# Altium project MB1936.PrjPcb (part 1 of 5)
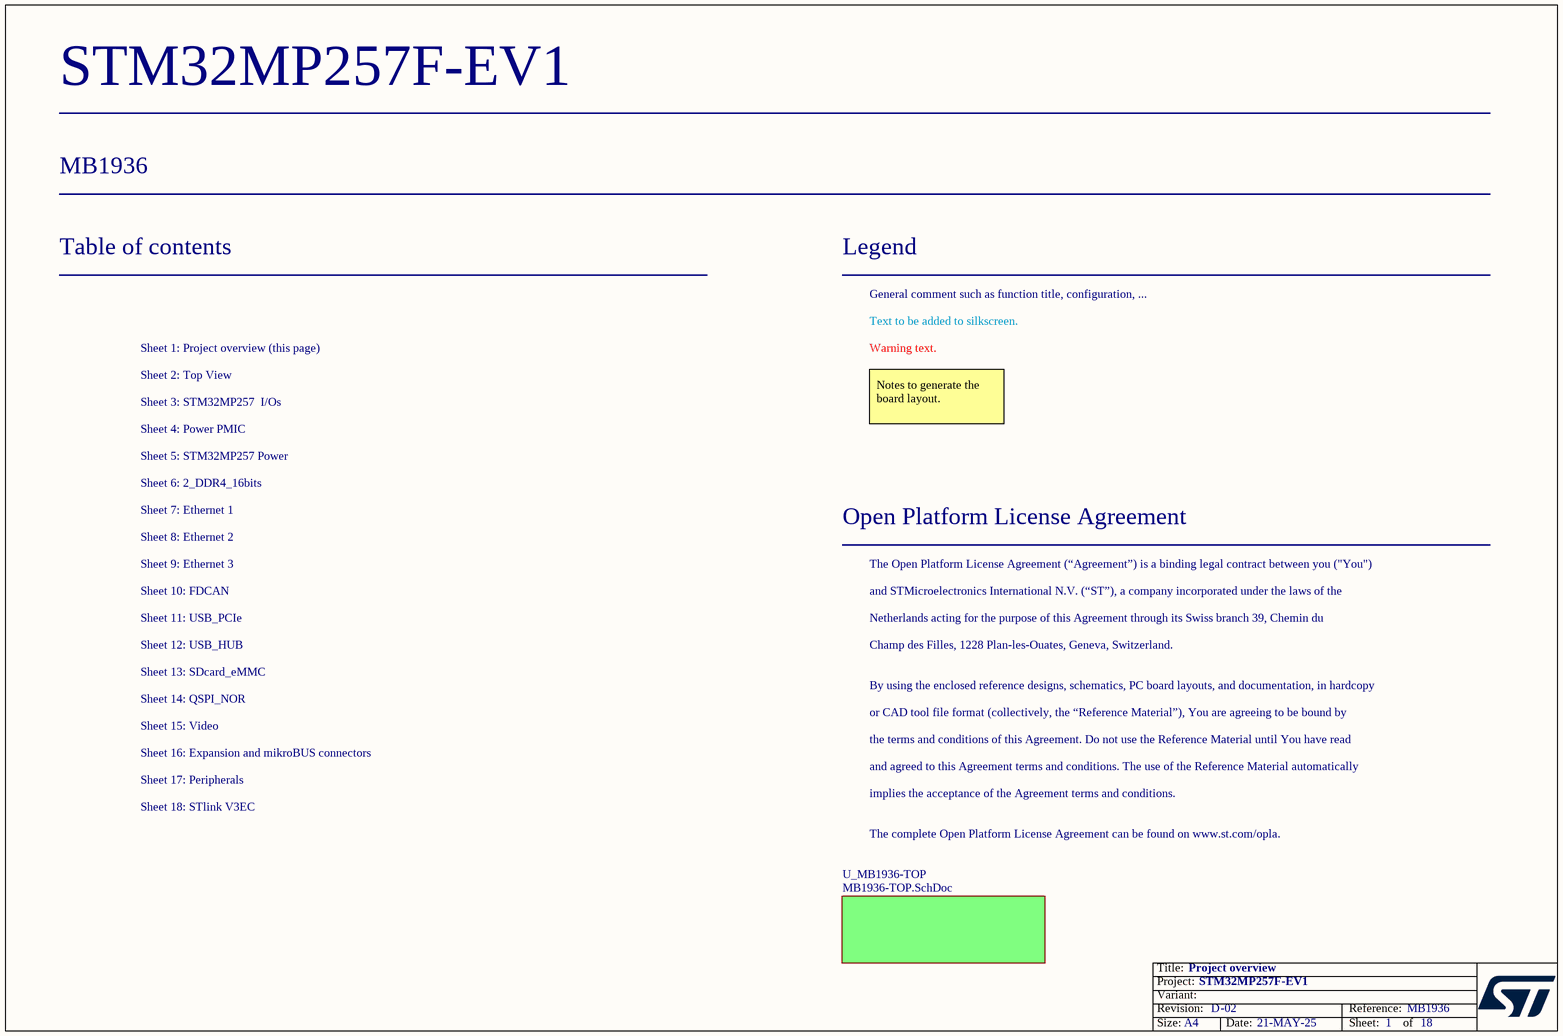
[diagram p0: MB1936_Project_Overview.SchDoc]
Board_Assembly_Revision: 02; Board_Document_Date: 21-MAY-25; Board_Name: STM32MP257F-EV1; Board_PCB_Revision: D; Board_Reference: MB1936
18 sheets, 865 parts. Net scope: flat (ports and power ports of the same name join across sheets).
Board file: MB1936.PcbDoc
Sheets:
  MB1936_Project_Overview.SchDoc
    U_MB1936-TOP = MB1936-TOP.SchDoc
      U_Video = Video.SchDoc
      U_SDcard_eMMC = SDcard_eMMC.SchDoc
      U_MP257_18x18 = MP257_18x18.SchDoc
      U_FDCAN = FDCAN.SchDoc
      U_Ethernet1 = Ethernet1.SchDoc
      U_Ethernet2 = Ethernet2.SchDoc
      U_Ethernet3 = Ethernet3.SchDoc
      U_Peripherals = Peripherals.SchDoc
      U_QSPI_NOR = QSPI_NOR.SchDoc
      U_Power_MPU = Power_MPU.SchDoc
      U_USB_HUB = USB_HUB.SchDoc
      U_2_DDR4_16bits = 2_DDR4_16bits.SchDoc
      U_USB_PCIe = USB_PCIe.SchDoc
      U_STLINK_V3EC = STLINK_V3EC.SchDoc
      U_Power_PMIC = Power_PMIC.SchDoc
      U_Expansion _&_mikroBUS_Connectors = Expansion _&_mikroBUS_Connectors.SchDoc

## Sheet MB1936_Project_Overview.SchDoc: Project overview
size A4; Date: Not used; ApprovedBy: Not used; CheckedBy: Not used; Author: Not used; CompanyName: STMicroelectronics; DrawnBy: Not used; Engineer: Not used; Organization: Not used; Address1: Not used; Address2: Not used; Address3: Not used; Address4: Not used; DocumentNumber: Not used; Revision: Not used; SheetNumber: 1; SheetTotal: 18

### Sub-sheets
U_MB1936-TOP = MB1936-TOP.SchDoc: no entries

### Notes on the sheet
- Table of contents
- Legend
- General comment such as function title, configuration, ...
- Sheet 1: Project overview (this page)
- Sheet 2: Top View
- Text to be added to silkscreen.
- Warning text.
- Sheet 3: STM32MP257  I/Os
- Sheet 4: Power PMIC
- Notes to generate the board layout.
- Sheet 5: STM32MP257 Power
- Sheet 7: Ethernet 1
- Sheet 6: 2_DDR4_16bits
- Sheet 8: Ethernet 2
- Sheet 9: Ethernet 3
- Open Platform License Agreement
- The Open Platform License Agreement (“Agreement”) is a binding legal contract between you ("You")
- Sheet 10: FDCAN
- Sheet 11: USB_PCIe
- Sheet 12: USB_HUB
- and STMicroelectronics International N.V. (“ST”), a company incorporated under the laws of the
- Netherlands acting for the purpose of this Agreement through its Swiss branch 39, Chemin du
- Champ des Filles, 1228 Plan-les-Ouates, Geneva, Switzerland.
- Sheet 13: SDcard_eMMC
- Sheet 14: QSPI_NOR
- By using the enclosed reference designs, schematics, PC board layouts, and documentation, in hardcopy
- or CAD tool file format (collectively, the “Reference Material”), You are agreeing to be bound by
- Sheet 17: Peripherals
- Sheet 16: Expansion and mikroBUS connectors
- Sheet 15: Video
- the terms and conditions of this Agreement. Do not use the Reference Material until You have read
- and agreed to this Agreement terms and conditions. The use of the Reference Material automatically
- Sheet 18: STlink V3EC
- implies the acceptance of the Agreement terms and conditions.
- The complete Open Platform License Agreement can be found on www.st.com/opla.

## Sheet MB1936-TOP.SchDoc: TOP
size A3; Date: Not used; ApprovedBy: Not used; CheckedBy: Not used; Author: Not used; CompanyName: STMicroelectronics; DrawnBy: Not used; Engineer: Not used; Organization: Not used; Address1: Not used; Address2: Not used; Address3: Not used; Address4: Not used; DocumentNumber: Not used; Revision: Not used; SheetNumber: 2; SheetTotal: 18
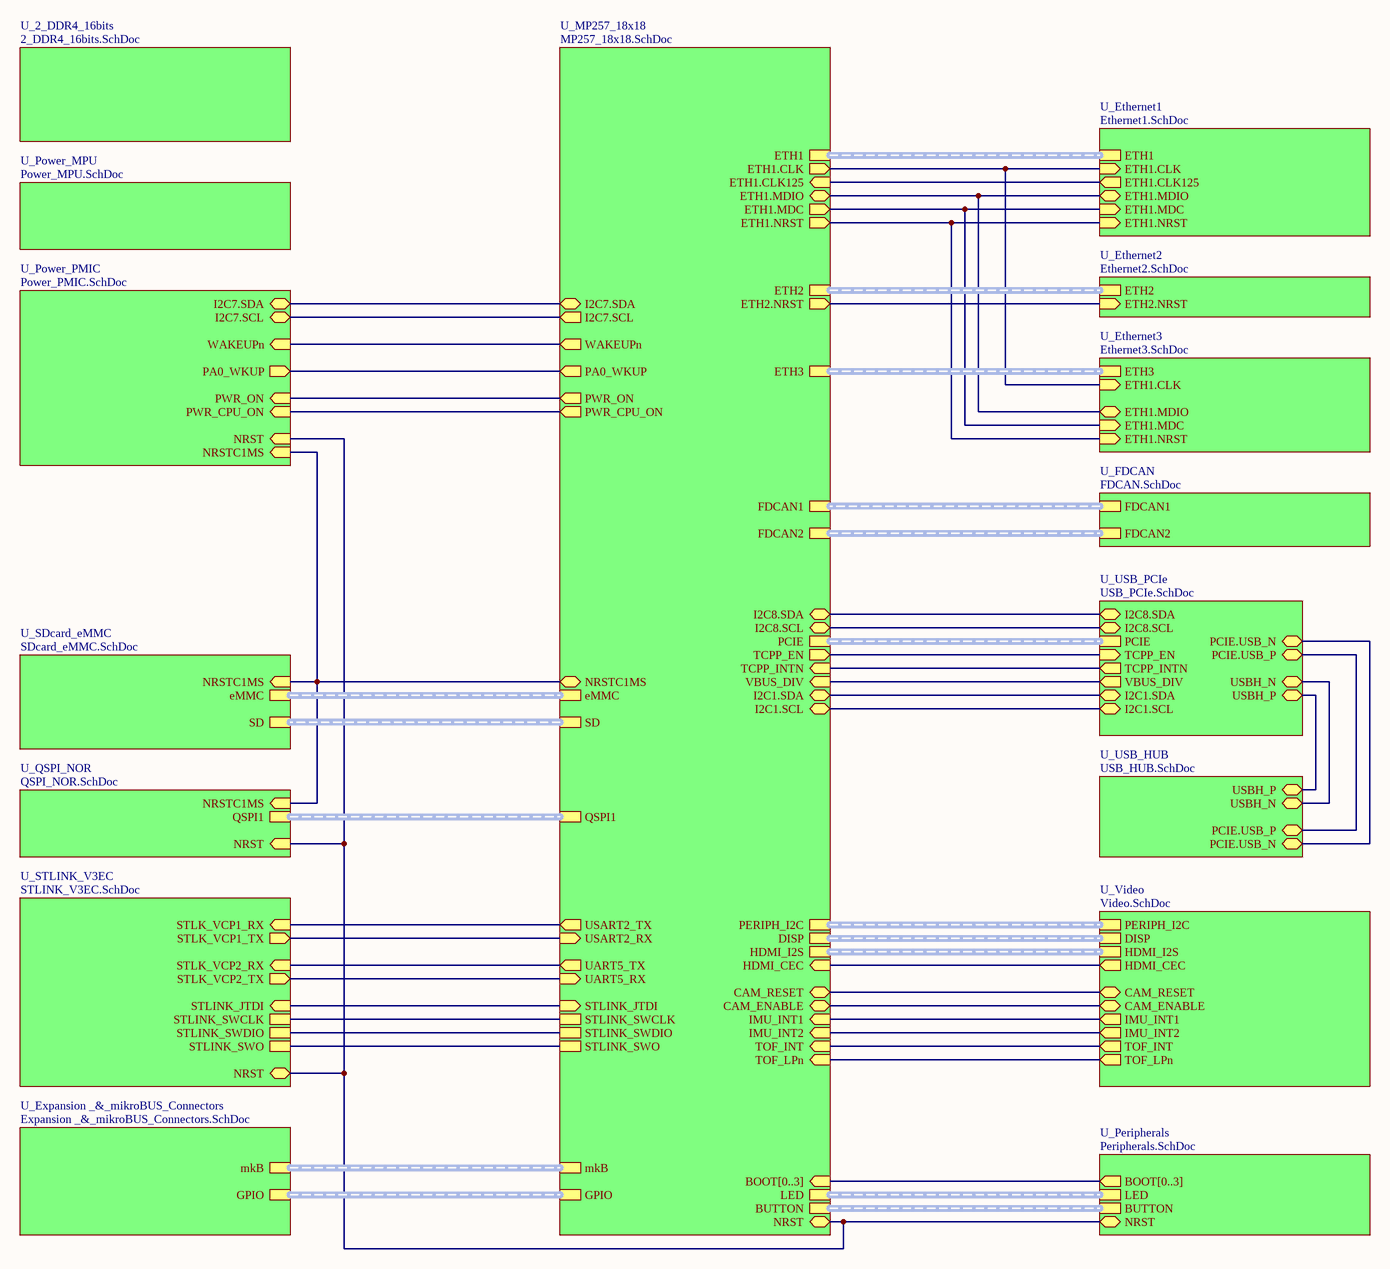
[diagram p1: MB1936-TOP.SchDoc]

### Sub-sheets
U_2_DDR4_16bits = 2_DDR4_16bits.SchDoc: no entries
U_Ethernet1 = Ethernet1.SchDoc: ETH1.NRST (in), ETH1 (harness ETH1), ETH1.CLK (in), ETH1.MDC (in), ETH1.MDIO (bidir), ETH1.CLK125 (out)
U_Ethernet2 = Ethernet2.SchDoc: ETH2.NRST (in), ETH2 (harness ETH2)
U_Ethernet3 = Ethernet3.SchDoc: ETH1.NRST (in), ETH3 (harness ETH3), ETH1.CLK (in), ETH1.MDIO (bidir), ETH1.MDC (in)
U_Expansion _&_mikroBUS_Connectors = Expansion _&_mikroBUS_Connectors.SchDoc: GPIO (harness GPIO), mkB (harness mikroBUS)
U_FDCAN = FDCAN.SchDoc: FDCAN2 (harness FDCAN2), FDCAN1 (harness FDCAN1)
U_MP257_18x18 = MP257_18x18.SchDoc: SD (harness SD), eMMC (harness eMMC), ETH1 (harness ETH1), ETH3 (harness ETH3), HDMI_CEC (in), ETH2 (harness ETH2), ETH1.NRST (out), PWR_ON (out), NRST (bidir), FDCAN1 (harness FDCAN1), FDCAN2 (harness FDCAN2), LED (harness LED), BOOT[0..3] (in), UART5_RX (in), UART5_TX (out), QSPI1 (harness QSPI), GPIO (harness GPIO), HDMI_I2S (harness HDMI_I2S), PERIPH_I2C (harness PERIPH_I2C), TCPP_INTN (in), I2C7.SDA (bidir), USART2_TX (out), I2C7.SCL (out), USART2_RX (in), VBUS_DIV (in), ETH1.MDIO (bidir), ETH1.CLK125 (in), ETH1.MDC (out), ETH1.CLK (out), PCIE (harness PCIE), STLINK_JTDI (in), STLINK_SWCLK, STLINK_SWDIO, STLINK_SWO, DISP (harness DISP), I2C1.SDA (bidir), I2C1.SCL (bidir), NRSTC1MS (bidir), PWR_CPU_ON (out), TOF_INT (in), CAM_ENABLE (bidir), IMU_INT1 (in), IMU_INT2 (in), TOF_LPn (in), CAM_RESET (bidir), ETH2.NRST (out), I2C8.SDA (bidir), I2C8.SCL (bidir), BUTTON (harness BUTTON), PA0_WKUP (out), WAKEUPn (out), mkB (harness mikroBUS), TCPP_EN (out)
U_Peripherals = Peripherals.SchDoc: NRST (bidir), BOOT[0..3] (out), LED (harness LED), BUTTON (harness BUTTON)
U_Power_MPU = Power_MPU.SchDoc: no entries
U_Power_PMIC = Power_PMIC.SchDoc: PWR_CPU_ON (in), NRST (in), PWR_ON (in), I2C7.SDA (bidir), I2C7.SCL (bidir), WAKEUPn (in), NRSTC1MS (in), PA0_WKUP (out)
U_QSPI_NOR = QSPI_NOR.SchDoc: QSPI1 (harness QSPI), NRSTC1MS (in), NRST (in)
U_SDcard_eMMC = SDcard_eMMC.SchDoc: SD (harness SD), NRSTC1MS (in), eMMC (harness eMMC)
U_STLINK_V3EC = STLINK_V3EC.SchDoc: NRST (bidir), STLK_VCP2_TX (out), STLK_VCP2_RX (in), STLK_VCP1_TX (out), STLK_VCP1_RX (in), STLINK_SWCLK, STLINK_SWDIO, STLINK_JTDI (in), STLINK_SWO
U_USB_HUB = USB_HUB.SchDoc: USBH_P (bidir), USBH_N (bidir), PCIE.USB_P (bidir), PCIE.USB_N (bidir)
U_USB_PCIe = USB_PCIe.SchDoc: PCIE (harness PCIE), USBH_P (bidir), USBH_N (bidir), TCPP_INTN (out), I2C1.SDA (bidir), I2C1.SCL (bidir), VBUS_DIV (out), PCIE.USB_N (bidir), PCIE.USB_P (bidir), I2C8.SDA (bidir), I2C8.SCL (bidir), TCPP_EN (in)
U_Video = Video.SchDoc: CAM_RESET (bidir), HDMI_CEC (out), CAM_ENABLE (bidir), HDMI_I2S (harness HDMI_I2S), PERIPH_I2C (harness PERIPH_I2C), DISP (harness DISP), IMU_INT1 (out), TOF_INT (out), TOF_LPn (out), IMU_INT2 (out)

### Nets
(unnamed): sheet U_Video/CAM_RESET, sheet U_MP257_18x18/CAM_RESET
(unnamed): sheet U_Video/HDMI_CEC, sheet U_MP257_18x18/HDMI_CEC  [a separate net that carries the same name]
(unnamed): sheet U_Video/CAM_ENABLE, sheet U_MP257_18x18/CAM_ENABLE  [a separate net that carries the same name]
(unnamed): sheet U_Video/IMU_INT1, sheet U_MP257_18x18/IMU_INT1  [a separate net that carries the same name]
(unnamed): sheet U_Video/TOF_INT, sheet U_MP257_18x18/TOF_INT  [a separate net that carries the same name]
(unnamed): sheet U_Video/TOF_LPn, sheet U_MP257_18x18/TOF_LPn  [a separate net that carries the same name]
(unnamed): sheet U_Video/IMU_INT2, sheet U_MP257_18x18/IMU_INT2  [a separate net that carries the same name]
(unnamed): sheet U_SDcard_eMMC/NRSTC1MS, sheet U_MP257_18x18/NRSTC1MS, sheet U_QSPI_NOR/NRSTC1MS, sheet U_Power_PMIC/NRSTC1MS  [a separate net that carries the same name]
(unnamed): sheet U_MP257_18x18/ETH1.NRST, sheet U_Ethernet1/ETH1.NRST, sheet U_Ethernet3/ETH1.NRST  [a separate net that carries the same name]
(unnamed): sheet U_MP257_18x18/PWR_ON, sheet U_Power_PMIC/PWR_ON  [a separate net that carries the same name]
(unnamed): sheet U_MP257_18x18/NRST, sheet U_Peripherals/NRST, sheet U_QSPI_NOR/NRST, sheet U_STLINK_V3EC/NRST, sheet U_Power_PMIC/NRST  [a separate net that carries the same name]
(unnamed): sheet U_MP257_18x18/UART5_RX, sheet U_STLINK_V3EC/STLK_VCP2_TX  [a separate net that carries the same name]
(unnamed): sheet U_MP257_18x18/UART5_TX, sheet U_STLINK_V3EC/STLK_VCP2_RX  [a separate net that carries the same name]
(unnamed): sheet U_MP257_18x18/TCPP_INTN, sheet U_USB_PCIe/TCPP_INTN  [a separate net that carries the same name]
(unnamed): sheet U_MP257_18x18/I2C7.SDA, sheet U_Power_PMIC/I2C7.SDA  [a separate net that carries the same name]
(unnamed): sheet U_MP257_18x18/USART2_TX, sheet U_STLINK_V3EC/STLK_VCP1_RX  [a separate net that carries the same name]
(unnamed): sheet U_MP257_18x18/I2C7.SCL, sheet U_Power_PMIC/I2C7.SCL  [a separate net that carries the same name]
(unnamed): sheet U_MP257_18x18/USART2_RX, sheet U_STLINK_V3EC/STLK_VCP1_TX  [a separate net that carries the same name]
(unnamed): sheet U_MP257_18x18/VBUS_DIV, sheet U_USB_PCIe/VBUS_DIV  [a separate net that carries the same name]
(unnamed): sheet U_MP257_18x18/ETH1.MDIO, sheet U_Ethernet1/ETH1.MDIO, sheet U_Ethernet3/ETH1.MDIO  [a separate net that carries the same name]
(unnamed): sheet U_MP257_18x18/ETH1.CLK125, sheet U_Ethernet1/ETH1.CLK125  [a separate net that carries the same name]
(unnamed): sheet U_MP257_18x18/ETH1.MDC, sheet U_Ethernet1/ETH1.MDC, sheet U_Ethernet3/ETH1.MDC  [a separate net that carries the same name]
(unnamed): sheet U_MP257_18x18/ETH1.CLK, sheet U_Ethernet1/ETH1.CLK, sheet U_Ethernet3/ETH1.CLK  [a separate net that carries the same name]
(unnamed): sheet U_MP257_18x18/STLINK_JTDI, sheet U_STLINK_V3EC/STLINK_JTDI  [a separate net that carries the same name]
(unnamed): sheet U_MP257_18x18/STLINK_SWCLK, sheet U_STLINK_V3EC/STLINK_SWCLK  [a separate net that carries the same name]
(unnamed): sheet U_MP257_18x18/STLINK_SWDIO, sheet U_STLINK_V3EC/STLINK_SWDIO  [a separate net that carries the same name]
(unnamed): sheet U_MP257_18x18/STLINK_SWO, sheet U_STLINK_V3EC/STLINK_SWO  [a separate net that carries the same name]
(unnamed): sheet U_MP257_18x18/I2C1.SDA, sheet U_USB_PCIe/I2C1.SDA  [a separate net that carries the same name]
(unnamed): sheet U_MP257_18x18/I2C1.SCL, sheet U_USB_PCIe/I2C1.SCL  [a separate net that carries the same name]
(unnamed): sheet U_MP257_18x18/PWR_CPU_ON, sheet U_Power_PMIC/PWR_CPU_ON  [a separate net that carries the same name]
(unnamed): sheet U_MP257_18x18/ETH2.NRST, sheet U_Ethernet2/ETH2.NRST  [a separate net that carries the same name]
(unnamed): sheet U_MP257_18x18/I2C8.SDA, sheet U_USB_PCIe/I2C8.SDA  [a separate net that carries the same name]
(unnamed): sheet U_MP257_18x18/I2C8.SCL, sheet U_USB_PCIe/I2C8.SCL  [a separate net that carries the same name]
(unnamed): sheet U_MP257_18x18/PA0_WKUP, sheet U_Power_PMIC/PA0_WKUP  [a separate net that carries the same name]
(unnamed): sheet U_MP257_18x18/WAKEUPn, sheet U_Power_PMIC/WAKEUPn  [a separate net that carries the same name]
(unnamed): sheet U_MP257_18x18/TCPP_EN, sheet U_USB_PCIe/TCPP_EN  [a separate net that carries the same name]
(unnamed): sheet U_USB_HUB/USBH_P, sheet U_USB_PCIe/USBH_P  [a separate net that carries the same name]
(unnamed): sheet U_USB_HUB/USBH_N, sheet U_USB_PCIe/USBH_N  [a separate net that carries the same name]
(unnamed): sheet U_USB_HUB/PCIE.USB_P, sheet U_USB_PCIe/PCIE.USB_P  [a separate net that carries the same name]
(unnamed): sheet U_USB_HUB/PCIE.USB_N, sheet U_USB_PCIe/PCIE.USB_N  [a separate net that carries the same name]

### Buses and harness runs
bus sheet U_MP257_18x18/BOOT[0..3] = sheet U_Peripherals/BOOT[0..3]
harness sheet U_Ethernet1/ETH1 = sheet U_MP257_18x18/ETH1
harness sheet U_Ethernet2/ETH2 = sheet U_MP257_18x18/ETH2
harness sheet U_Ethernet3/ETH3 = sheet U_MP257_18x18/ETH3
harness sheet U_Expansion _&_mikroBUS_Connectors/GPIO = sheet U_MP257_18x18/GPIO
harness sheet U_Expansion _&_mikroBUS_Connectors/mkB = sheet U_MP257_18x18/mkB
harness sheet U_FDCAN/FDCAN1 = sheet U_MP257_18x18/FDCAN1
harness sheet U_FDCAN/FDCAN2 = sheet U_MP257_18x18/FDCAN2
harness sheet U_MP257_18x18/BUTTON = sheet U_Peripherals/BUTTON
harness sheet U_MP257_18x18/DISP = sheet U_Video/DISP
harness sheet U_MP257_18x18/eMMC = sheet U_SDcard_eMMC/eMMC
harness sheet U_MP257_18x18/HDMI_I2S = sheet U_Video/HDMI_I2S
harness sheet U_MP257_18x18/LED = sheet U_Peripherals/LED
harness sheet U_MP257_18x18/PCIE = sheet U_USB_PCIe/PCIE
harness sheet U_MP257_18x18/PERIPH_I2C = sheet U_Video/PERIPH_I2C
harness sheet U_MP257_18x18/QSPI1 = sheet U_QSPI_NOR/QSPI1
harness sheet U_MP257_18x18/SD = sheet U_SDcard_eMMC/SD

## Sheet Video.SchDoc: VIDEO
size A3; Date: Not used; ApprovedBy: Not used; CheckedBy: Not used; Author: Not used; CompanyName: STMicroelectronics; DrawnBy: Not used; Engineer: Not used; Organization: Not used; Address1: Not used; Address2: Not used; Address3: Not used; Address4: Not used; DocumentNumber: Not used; Revision: Not used; SheetNumber: 15; SheetTotal: 18
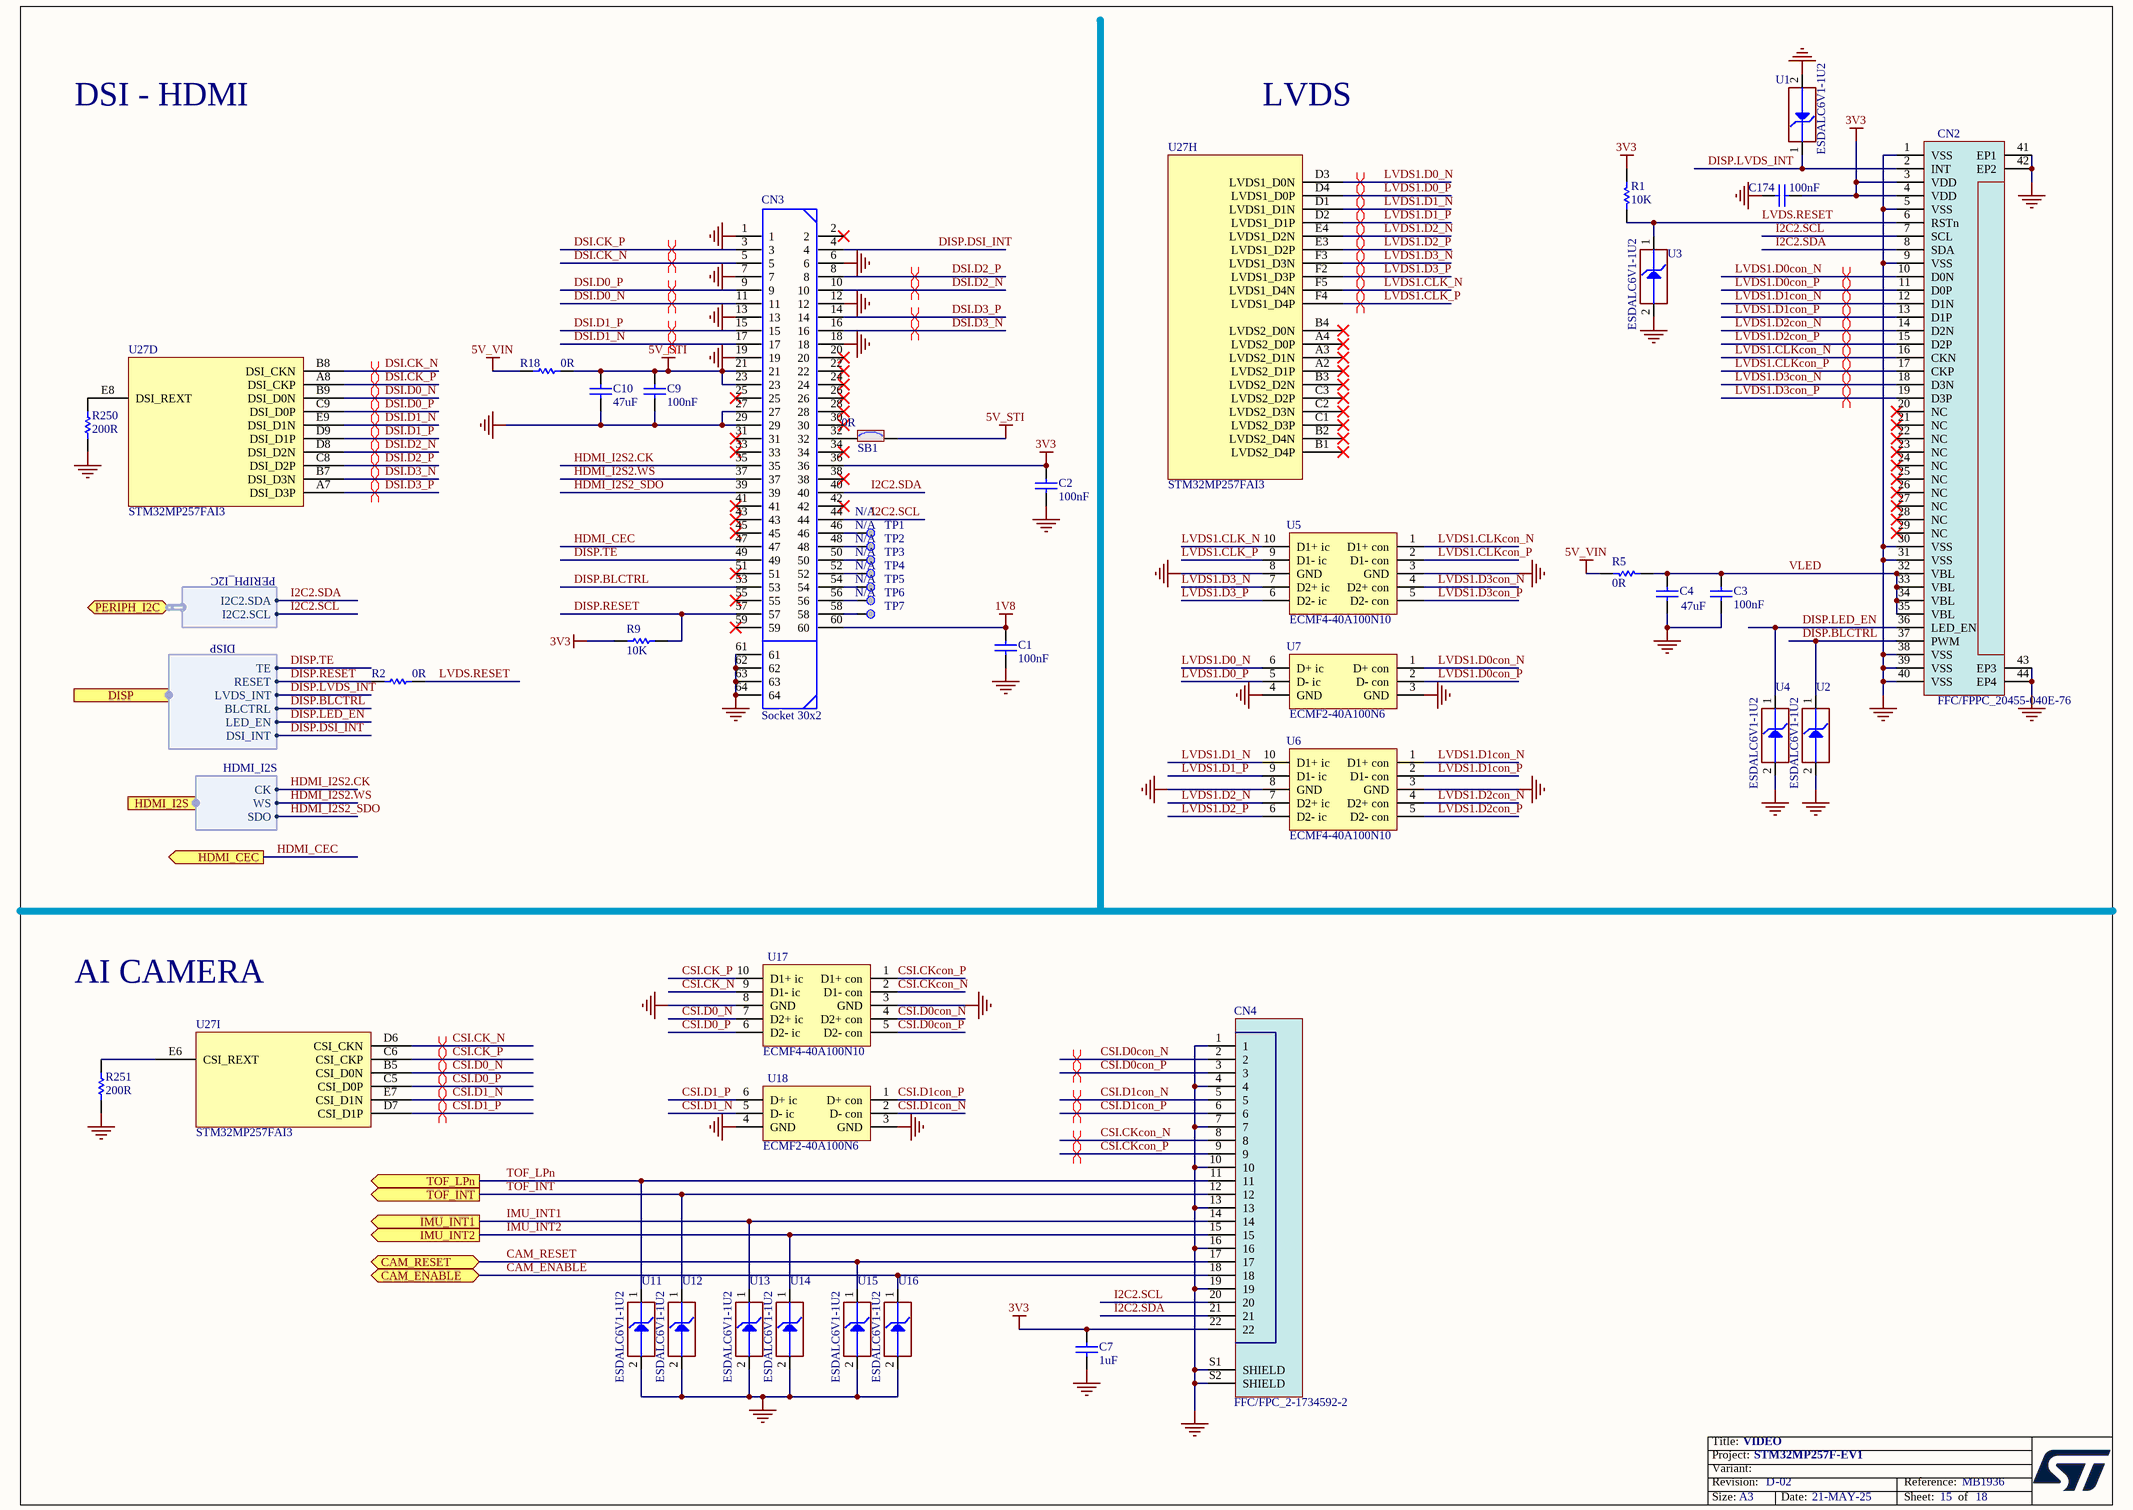
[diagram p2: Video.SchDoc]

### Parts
C1  value 100nF  [C0402]  (hidden comment: Capacitor)
C2  value 100nF  [C0402]  (hidden comment: Capacitor)
C3  value 100nF  [C0402]  (hidden comment: Capacitor)
C4  value 47uF  [C0805]  (hidden comment: Capacitor)
C7  value 1uF  [C0402]  (hidden comment: Capacitor)
C9  value 100nF  [C0402]  (hidden comment: Capacitor)
C10  value 47uF  [C0805]  (hidden comment: Capacitor)
C174  value 100nF  [C0402]  (hidden comment: Capacitor)
CN2  value FFC/FPPC_20455-040E-76  [CON_I-PEX_20455-040E-76]  (hidden comment: IPEX20455)
CN3  value Socket 30x2  [CON_SAMTEC_QSH-030-01-F-D-A]  (hidden comment: Socket QSH-030-01-F-D-A)
CN4  value FFC/FPC_2-1734592-2  [CON_TE-CONNECTIVITY_2-1734592-2_INV]  (hidden comment: 2-1734592-2)
R1  value 10K  [R0402]  (hidden comment: Resistor)
R2  value 0R  [R0402]  (hidden comment: Resistor)
R5  value 0R  [R0805]  (hidden comment: Resistor)
R9  value 10K  [R0402]  (hidden comment: Resistor)
R18  value 0R  [R0402]  (hidden comment: Resistor)
R250  value 200R  [R0402]  (hidden comment: Resistor)
R251  value 200R  [R0402]  (hidden comment: Resistor)
SB1  value 0R  [SOLDER-BRIDGE_R0603-0R]  (hidden comment: SB_ON)
TP1  Test Point  [TP_SMD_1MM]  (value not drawn)  (no BOM)
TP2  Test Point  [TP_SMD_1MM]  (value not drawn)  (no BOM)
TP3  Test Point  [TP_SMD_1MM]  (value not drawn)  (no BOM)
TP4  Test Point  [TP_SMD_1MM]  (value not drawn)  (no BOM)
TP5  Test Point  [TP_SMD_1MM]  (value not drawn)  (no BOM)
TP6  Test Point  [TP_SMD_1MM]  (value not drawn)  (no BOM)
TP7  Test Point  [TP_SMD_1MM]  (value not drawn)  (no BOM)
U1  value ESDALC6V1-1U2  [ESD_ST0201]  (hidden comment: ESD-TRANSIL)
U2  value ESDALC6V1-1U2  [ESD_ST0201]  (hidden comment: ESD-TRANSIL)
U3  value ESDALC6V1-1U2  [ESD_ST0201]  (hidden comment: ESD-TRANSIL)
U4  value ESDALC6V1-1U2  [ESD_ST0201]  (hidden comment: ESD-TRANSIL)
U5  ECMF4-40A100N10  [ESD_UQFN-10L_2P25X1P4_P040]
U6  ECMF4-40A100N10  [ESD_UQFN-10L_2P25X1P4_P040]
U7  ECMF2-40A100N6  [ESD_UQFN-6L_1P45X1P4_P040]
U11  value ESDALC6V1-1U2  [ESD_ST0201]  (hidden comment: ESD-TRANSIL)
U12  value ESDALC6V1-1U2  [ESD_ST0201]  (hidden comment: ESD-TRANSIL)
U13  value ESDALC6V1-1U2  [ESD_ST0201]  (hidden comment: ESD-TRANSIL)
U14  value ESDALC6V1-1U2  [ESD_ST0201]  (hidden comment: ESD-TRANSIL)
U15  value ESDALC6V1-1U2  [ESD_ST0201]  (hidden comment: ESD-TRANSIL)
U16  value ESDALC6V1-1U2  [ESD_ST0201]  (hidden comment: ESD-TRANSIL)
U17  ECMF4-40A100N10  [ESD_UQFN-10L_2P25X1P4_P040]
U18  ECMF2-40A100N6  [ESD_UQFN-6L_1P45X1P4_P040]
U27  STM32MP257FAI3  [ICC_LFBGA436_18X18_P080_H1P70_STM32MP257_CODE-B0D1]  (parts D,H,I of 9)

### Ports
CAM_ENABLE (bidir), CAM_RESET (bidir), DISP (harness DISP), HDMI_CEC (out), HDMI_I2S (harness HDMI_I2S), IMU_INT1 (out), IMU_INT2 (out), PERIPH_I2C (bidir, harness PERIPH_I2C), TOF_INT (out), TOF_LPn (out)

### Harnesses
DISP: RESET, TE, LVDS_INT, BLCTRL, LED_EN, DSI_INT
HDMI_I2S: CK, SDO, WS
PERIPH_I2C: I2C2.SDA, I2C2.SCL

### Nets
1V8: C1.2 CN3.60
3V3: C2.2 C7.2 C174.2 CN2.3(VDD) CN2.4(VDD) CN3.36 CN4.22 R1.1 R9.1
5V_STI: C9.2 C10.2 CN3.21 CN3.23 R18.2 SB1.2
5V_VIN: R5.2 R18.1
GND: C1.1 C2.1 C3.1 C4.1 C7.1 C9.1 C10.1 C174.1 CN2.1(VSS) CN2.5(VSS) CN2.9(VSS) CN2.30(VSS) CN2.31(VSS) CN2.38(VSS) CN2.39(VSS) CN2.40(VSS) CN2.41(EP1) CN2.42(EP2) CN2.43(EP3) CN2.44(EP4) CN3.1 CN3.6 CN3.7 CN3.12 CN3.13 CN3.18 CN3.19 CN3.27 CN3.29 CN3.61 CN3.62 CN3.63 CN3.64 CN4.1 CN4.4 CN4.7 CN4.10 CN4.13 CN4.16 CN4.19 CN4.S1(SHIELD) CN4.S2(SHIELD) R250.2 R251.2 U1.2(GND) U2.2(GND) U3.2(GND) U4.2(GND) U5.3(GND) U5.8(GND) U6.3(GND) U6.8(GND) U7.3(GND) U7.4(GND) U11.2(GND) U12.2(GND) U13.2(GND) U14.2(GND) U15.2(GND) U16.2(GND) U17.3(GND) U17.8(GND) U18.3(GND) U18.4(GND)
CAM_ENABLE: CN4.18 U16.1(IO1) ; port CAM_ENABLE
CAM_RESET: CN4.17 U15.1(IO1) ; port CAM_RESET
CSI.CK_N: U17.9(D1-_ic) U27.D6(CSI_CKN)
CSI.CK_P: U17.10(D1+_ic) U27.C6(CSI_CKP)
CSI.CKcon_N: CN4.8 U17.2(D1-_con)
CSI.CKcon_P: CN4.9 U17.1(D1+_con)
CSI.D0_N: U17.7(D2+_ic) U27.B5(CSI_D0N)
CSI.D0_P: U17.6(D2-_ic) U27.C5(CSI_D0P)
CSI.D0con_N: CN4.2 U17.4(D2+_con)
CSI.D0con_P: CN4.3 U17.5(D2-_con)
CSI.D1_N: U18.5(D-_ic) U27.E7(CSI_D1N)
CSI.D1_P: U18.6(D+_ic) U27.D7(CSI_D1P)
CSI.D1con_N: CN4.5 U18.2(D-_con)
CSI.D1con_P: CN4.6 U18.1(D+_con)
DISP.BLCTRL: CN2.37(PWM) CN3.53 U2.1(IO1) ; port DISP.BLCTRL
DISP.DSI_INT: CN3.4 ; port DISP.DSI_INT
DISP.LED_EN: CN2.36(LED_EN) U4.1(IO1) ; port DISP.LED_EN
DISP.LVDS_INT: CN2.2(INT) U1.1(IO1) ; port DISP.LVDS_INT
DISP.RESET: CN3.57 R2.1 R9.2 ; port DISP.RESET
DISP.TE: CN3.49 ; port DISP.TE
DSI.CK_N: CN3.5 U27.B8(DSI_CKN)
DSI.CK_P: CN3.3 U27.A8(DSI_CKP)
DSI.D0_N: CN3.11 U27.B9(DSI_D0N)
DSI.D0_P: CN3.9 U27.C9(DSI_D0P)
DSI.D1_N: CN3.17 U27.E9(DSI_D1N)
DSI.D1_P: CN3.15 U27.D9(DSI_D1P)
DSI.D2_N: CN3.10 U27.D8(DSI_D2N)
DSI.D2_P: CN3.8 U27.C8(DSI_D2P)
DSI.D3_N: CN3.16 U27.B7(DSI_D3N)
DSI.D3_P: CN3.14 U27.A7(DSI_D3P)
HDMI_CEC: CN3.47 ; port HDMI_CEC
HDMI_I2S2.CK: CN3.35 ; port HDMI_I2S.CK
HDMI_I2S2.WS: CN3.37 ; port HDMI_I2S.WS
HDMI_I2S2_SDO: CN3.39 ; port HDMI_I2S.SDO
I2C2.SCL: CN2.7(SCL) CN3.44 CN4.20 ; port PERIPH_I2C.I2C2.SCL
I2C2.SDA: CN2.8(SDA) CN3.40 CN4.21 ; port PERIPH_I2C.I2C2.SDA
IMU_INT1: CN4.14 U13.1(IO1) ; port IMU_INT1
IMU_INT2: CN4.15 U14.1(IO1) ; port IMU_INT2
LVDS1.CLK_N: U5.10(D1+_ic) U27.F5(LVDS1_D4N)
LVDS1.CLK_P: U5.9(D1-_ic) U27.F4(LVDS1_D4P)
LVDS1.CLKcon_N: CN2.16(CKN) U5.1(D1+_con)
LVDS1.CLKcon_P: CN2.17(CKP) U5.2(D1-_con)
LVDS1.D0_N: U7.6(D+_ic) U27.D3(LVDS1_D0N)
LVDS1.D0_P: U7.5(D-_ic) U27.D4(LVDS1_D0P)
LVDS1.D0con_N: CN2.10(D0N) U7.1(D+_con)
LVDS1.D0con_P: CN2.11(D0P) U7.2(D-_con)
LVDS1.D1_N: U6.10(D1+_ic) U27.D1(LVDS1_D1N)
LVDS1.D1_P: U6.9(D1-_ic) U27.D2(LVDS1_D1P)
LVDS1.D1con_N: CN2.12(D1N) U6.1(D1+_con)
LVDS1.D1con_P: CN2.13(D1P) U6.2(D1-_con)
LVDS1.D2_N: U6.7(D2+_ic) U27.E4(LVDS1_D2N)
LVDS1.D2_P: U6.6(D2-_ic) U27.E3(LVDS1_D2P)
LVDS1.D2con_N: CN2.14(D2N) U6.4(D2+_con)
LVDS1.D2con_P: CN2.15(D2P) U6.5(D2-_con)
LVDS1.D3_N: U5.7(D2+_ic) U27.F3(LVDS1_D3N)
LVDS1.D3_P: U5.6(D2-_ic) U27.F2(LVDS1_D3P)
LVDS1.D3con_N: CN2.18(D3N) U5.4(D2+_con)
LVDS1.D3con_P: CN2.19(D3P) U5.5(D2-_con)
LVDS.RESET: CN2.6(RSTn) R1.2 R2.2 U3.1(IO1)
TOF_INT: CN4.12 U12.1(IO1) ; port TOF_INT
TOF_LPn: CN4.11 U11.1(IO1) ; port TOF_LPn
VLED: C3.2 C4.2 CN2.32(VBL) CN2.33(VBL) CN2.34(VBL) CN2.35(VBL) R5.1
NetCN3_32: CN3.32 SB1.1
NetCN3_46: CN3.46 TP1.1
NetCN3_48: CN3.48 TP2.1
NetCN3_50: CN3.50 TP3.1
NetCN3_52: CN3.52 TP4.1
NetCN3_54: CN3.54 TP5.1
NetCN3_56: CN3.56 TP6.1
NetCN3_58: CN3.58 TP7.1
NetR250_1: R250.1 U27.E8(DSI_REXT)
NetR251_1: R251.1 U27.E6(CSI_REXT)

Not connected (* = marked no-connect by the designer): CN2 20(NC)* 21(NC)* 22(NC)* 23(NC)* 24(NC)* 25(NC)* 26(NC)* 27(NC)* 28(NC)* 29(NC)*; CN3 2* 20* 22* 24* 25* 26* 28* 30* 31* 33* 34* 38* 41* 42* 43* 45* 51* 55* 59*; U27 A2(LVDS2_D1P)* A3(LVDS2_D1N)* A4(LVDS2_D0P)* B1(LVDS2_D4P)* B2(LVDS2_D4N)* B3(LVDS2_D2N)* B4(LVDS2_D0N)* C1(LVDS2_D3P)* C2(LVDS2_D3N)* C3(LVDS2_D2P)*

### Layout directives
differential pair: CSI.CK_N, CSI.CK_P, CSI.CKcon_N, CSI.CKcon_P, CSI.D0_N, CSI.D0_P, CSI.D0con_N, CSI.D0con_P, CSI.D1_N, CSI.D1_P, CSI.D1con_N, CSI.D1con_P, DSI.CK_N, DSI.CK_P, DSI.D0_N, DSI.D0_P, DSI.D1_N, DSI.D1_P, DSI.D2_N, DSI.D2_P, DSI.D3_N, DSI.D3_P, LVDS1.CLK_N, LVDS1.CLK_P, LVDS1.CLKcon_N, LVDS1.CLKcon_P, LVDS1.D0_N, LVDS1.D0_P, LVDS1.D0con_N, LVDS1.D0con_P, LVDS1.D1_N, LVDS1.D1_P, LVDS1.D1con_N, LVDS1.D1con_P, LVDS1.D2_N, LVDS1.D2_P, LVDS1.D2con_N, LVDS1.D2con_P, LVDS1.D3_N, LVDS1.D3_P, LVDS1.D3con_N, LVDS1.D3con_P

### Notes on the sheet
- DSI - HDMI
- LVDS
- AI CAMERA

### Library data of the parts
C1-C3 C9 C174 = MCD-02352: Capacitor, MLCC, 100nF, 10V, X5R, +/-10%, 0402, T=0,5mm; Part_Preference: Recommended; Manufacturer: YAGEO; Manufacturer_Part_Number: CC0402KRX5R6BB104; Partial_Alternate_Internal_Part_Number: MCD-04357; Component_Country_Of_Origin: China; ShowFields: YES; ID: 4458
C4 C10 = MCD-00204: Capacitor, MLCC, 47uF, 10V, X5R, +/-20%, 0805, T=1.25mm; Part_Preference: Recommended; Manufacturer: MURATA; Manufacturer_Part_Number: GRM21BR61A476ME15; Component_Country_Of_Origin: Japan°°; ShowFields: YES; ID: 2664
C7 = MCD-00095: Capacitor, MLCC, 1uF, 25V, X5R, +/-10%, 0402, T=0,5mm; Manufacturer_Part_Number: GRM155R61E105KA12; Manufacturer: MURATA; Part_Preference: Recommended; Alternate_Manufacturer_Part_Number: GRM155R60J105KE19; Partial_Alternate_Internal_Part_Number: MCD-04188; Order_Code_RS: 2218855; Component_Country_Of_Origin: Japan°°; ID: 2772; ShowFields: YES
CN2 = MCD-03562: Socket_FFC/FPC, 40pins, 0.5mm, RA, SMD, T=1mm; Part_Type: Connector; Part_Preference: Recommended; Manufacturer: I-PEX; Manufacturer_Part_Number: 20455-040E-76; Component_Country_Of_Origin: Singapore; ShowFields: YES; ID: 5678
CN3 = MCD-00137: Socket, 30x2, 0.5mm, VR, SMD, T=3.05mm; BMS_Part_Number: 9183715; Part_Preference: Recommended; Part_Type: Connector; Manufacturer: SAMTEC; Partial_Alternate_Internal_Part_Number: MCD-02128; Component_Country_Of_Origin: China, Costa Rica, Malaysia, USA, Vietnam; ID: 2732; Order_Code_RS: 180-2952; ShowFields: YES
CN4 = MCD-03600: Socket_FFC/FPC, 22pins, 0.5mm, RA, SMD, T=2mm; Part_Type: Connector; Part_Preference: Forbidden; Manufacturer: TE CONNECTIVITY; Partial_Alternate_Internal_Part_Number: MCD-04650; Component_Country_Of_Origin: China°; ShowFields: YES; ID: 5716
R1 R9 = MCD-00053: Resistor, 10K, 0402, +/-1%, 1/16W; BMS_Part_Number: 9131590; Part_Preference: Recommended; Manufacturer: YAGEO; Manufacturer_Part_Number: RC0402FR-0710KL; Order_Code_RS: 9239359; Component_Country_Of_Origin: China; ID: 2539; ShowFields: YES
R2 R18 = MCD-00052: Resistor, 0R, 0402, +/-5%, 1/16W; Part_Preference: Recommended; Manufacturer: YAGEO; Manufacturer_Part_Number: RC0402JR-070RL; Order_Code_RS: 9232516RL; Component_Country_Of_Origin: China; ID: 2540; ShowFields: YES
R5 = MCD-00179: Resistor, 0R, 0805, +/-5%, 1/8W; Part_Preference: Recommended; Manufacturer: YAGEO; Manufacturer_Part_Number: RC0805JR-070RL; Component_Country_Of_Origin: China; ID: 2685; ShowFields: YES
R250 R251 = MCD-00417: Resistor, 200R, 0402, +/-1%, 1/16W; Manufacturer_Part_Number: RC0402FR-07200RL; Manufacturer: YAGEO; Part_Preference: Recommended; Component_Country_Of_Origin: China; ID: 2860; ShowFields: YES
SB1 = MCD-00071: Solder Bridge ON; Part_Preference: Recommended; Part_Type: Resistor; Manufacturer: YAGEO; Manufacturer_Part_Number: RC0603JR-070RL; Manufacturer_HQ_COO: Unknown; ID: 2521; ShowFields: YES; Component_Country_Of_Origin: China; Order_Code_RS: 199-5647
TP1-TP7 = MCD-00074: Test Point 1mm; Part_Preference: Recommended; Part_Type: Misc; ID: 2518; ShowFields: YES; Component_Country_Of_Origin: Unknown
U1-U4 U11-U16 = MCD-00170: ESD protection 6V1; BMS_Part_Number: 9151132; Part_Type: Diode; Part_Preference: Recommended; Manufacturer: STMICROELECTRONICS; Manufacturer_HQ_COO: EU; Component_Country_Of_Origin: China; ShowFields: YES; ID: 2696; Order_Code_RS: 795-8404
U5 U6 U17 = MCD-03059: ESD protection & Common Filter High Speed serial Interfaces , 0.4 pitch; Part_Type: IC; Part_Preference: Recommended; Manufacturer: STMICROELECTRONICS; ShowFields: YES; ID: 5175; Component_Country_Of_Origin: China
U7 U18 = MCD-03060: ESD protection & Common Filter High Speed serial Interfaces , 0.4 pitch; Part_Type: IC; Part_Preference: Recommended; Manufacturer: STMICROELECTRONICS; ShowFields: YES; ID: 5176; Component_Country_Of_Origin: China
U27 = MCD-02000: MPU, ARM Cortex-A35 + M33 32-bit MPU, 808KB RAM, With Crypto; Part_Type: IC; Part_Preference: Recommended; Manufacturer: STMICROELECTRONICS; Manufacturer_HQ_COO: EU; Component_Country_Of_Origin: Unknown; ShowFields: YES; ID: 4100

## Sheet SDcard_eMMC.SchDoc: SDcard_eMMC
size A3; Date: Not used; ApprovedBy: Not used; CheckedBy: Not used; Author: Not used; CompanyName: STMicroelectronics; DrawnBy: Not used; Engineer: Not used; Organization: Not used; Address1: Not used; Address2: Not used; Address3: Not used; Address4: Not used; DocumentNumber: Not used; Revision: Not used; SheetNumber: 13; SheetTotal: 18
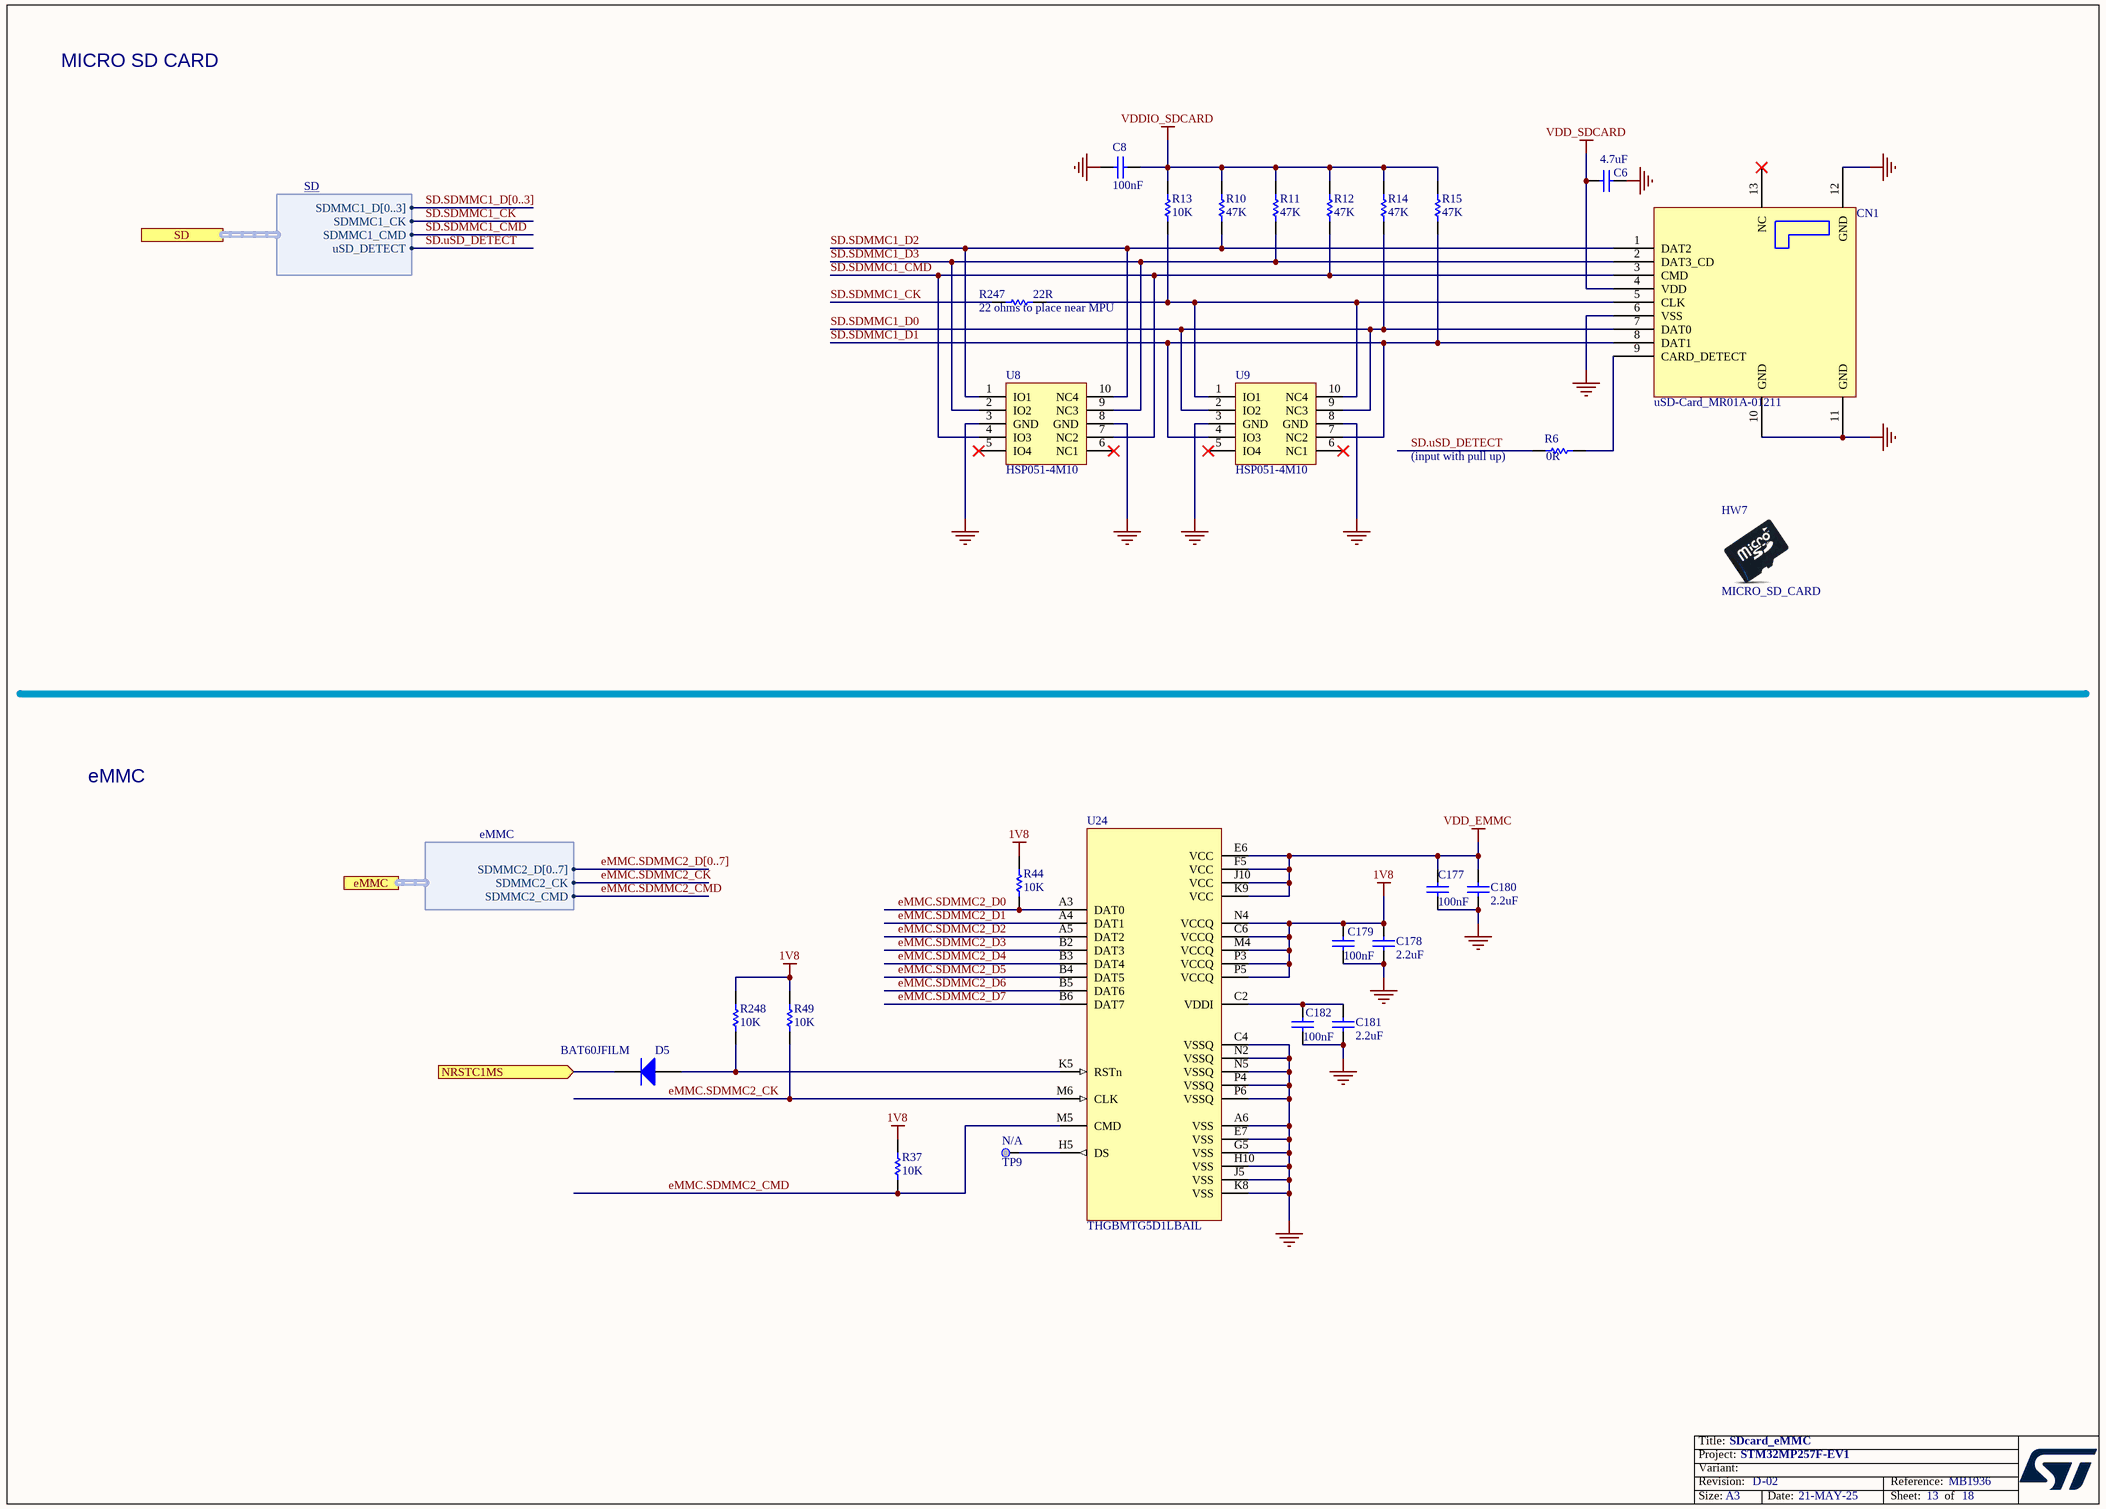
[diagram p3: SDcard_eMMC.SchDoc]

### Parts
C6  value 4.7uF  [C0402]  (hidden comment: Capacitor)
C8  value 100nF  [C0402]  (hidden comment: Capacitor)
C177  value 100nF  [C0402]  (hidden comment: Capacitor)
C178  value 2.2uF  [C0402]  (hidden comment: Capacitor)
C179  value 100nF  [C0402]  (hidden comment: Capacitor)
C180  value 2.2uF  [C0402]  (hidden comment: Capacitor)
C181  value 2.2uF  [C0402]  (hidden comment: Capacitor)
C182  value 100nF  [C0402]  (hidden comment: Capacitor)
CN1  value uSD-Card_MR01A-01211  [CON_MICROSD_ATOM_MR01A-01211]  (hidden comment: MR01A-01211)
D5  BAT60JFILM  [DIO_SOD323]
HW7  Micro_SD_card  (mechanical)
R6  value 0R  [R0402]  (hidden comment: Resistor)
R10  value 47K  [R0402]  (hidden comment: Resistor)
R11  value 47K  [R0402]  (hidden comment: Resistor)
R12  value 47K  [R0402]  (hidden comment: Resistor)
R13  value 10K  [R0402]  (hidden comment: Resistor)
R14  value 47K  [R0402]  (hidden comment: Resistor)
R15  value 47K  [R0402]  (hidden comment: Resistor)
R37  value 10K  [R0402]  (hidden comment: Resistor)
R44  value 10K  [R0402]  (hidden comment: Resistor)
R49  value 10K  [R0402]  (hidden comment: Resistor)
R247  value 22R  [R0201_H0P23]  (hidden comment: Resistor)
R248  value 10K  [R0402]  (hidden comment: Resistor)
TP9  Test Point  [TP_SMD_1MM]  (value not drawn)  (no BOM)
U8  HSP051-4M10  [ESD_UQFN-10L_2P5X1_P050]
U9  HSP051-4M10  [ESD_UQFN-10L_2P5X1_P050]
U24  value THGBMTG5D1LBAIL  [ICC_P-WFBGA153_13X11P5_P050]  (hidden comment: eMMC_THGBMTG5D1LBAIL)

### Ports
eMMC (harness eMMC), NRSTC1MS (in), SD (harness SD)

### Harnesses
SD: SDMMC1_D[0..3], SDMMC1_CK, SDMMC1_CMD, uSD_DETECT
eMMC: SDMMC2_CK, SDMMC2_CMD, SDMMC2_D[0..7]

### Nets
1V8: C178.2 C179.2 R37.2 R44.2 R49.2 R248.2 U24.C6(VCCQ) U24.M4(VCCQ) U24.N4(VCCQ) U24.P3(VCCQ) U24.P5(VCCQ)
GND: C6.1 C8.1 C177.1 C178.1 C179.1 C180.1 C181.1 C182.1 CN1.6(VSS) CN1.10(GND) CN1.11(GND) CN1.12(GND) U8.3(GND) U8.8(GND) U9.3(GND) U9.8(GND) U24.A6(VSS) U24.C4(VSSQ) U24.E7(VSS) U24.G5(VSS) U24.H10(VSS) U24.J5(VSS) U24.K8(VSS) U24.N2(VSSQ) U24.N5(VSSQ) U24.P4(VSSQ) U24.P6(VSSQ)
VDD_EMMC: C177.2 C180.2 U24.E6(VCC) U24.F5(VCC) U24.J10(VCC) U24.K9(VCC)
VDD_SDCARD: C6.2 CN1.4(VDD)
VDDIO_SDCARD: C8.2 R10.2 R11.2 R12.2 R13.2 R14.2 R15.2
eMMC.SDMMC2_CK: R49.1 U24.M6(CLK) ; port eMMC.SDMMC2_CK
eMMC.SDMMC2_CMD: R37.1 U24.M5(CMD) ; port eMMC.SDMMC2_CMD
eMMC.SDMMC2_D0: R44.1 U24.A3(DAT0)
eMMC.SDMMC2_D1: U24.A4(DAT1)
eMMC.SDMMC2_D2: U24.A5(DAT2)
eMMC.SDMMC2_D3: U24.B2(DAT3)
eMMC.SDMMC2_D4: U24.B3(DAT4)
eMMC.SDMMC2_D5: U24.B4(DAT5)
eMMC.SDMMC2_D6: U24.B5(DAT6)
eMMC.SDMMC2_D7: U24.B6(DAT7)
NRSTC1MS: D5.2(K) ; port NRSTC1MS
SD.SDMMC1_CK: R247.1 ; port SD.SDMMC1_CK
SD.SDMMC1_CMD: CN1.3(CMD) R12.1 U8.4(IO3) U8.7(NC2) ; port SD.SDMMC1_CMD
SD.SDMMC1_D0: CN1.7(DAT0) R14.1 U9.2(IO2) U9.9(NC3)
SD.SDMMC1_D1: CN1.8(DAT1) R15.1 U9.4(IO3) U9.7(NC2)
SD.SDMMC1_D2: CN1.1(DAT2) R10.1 U8.1(IO1) U8.10(NC4)
SD.SDMMC1_D3: CN1.2(DAT3_CD) R11.1 U8.2(IO2) U8.9(NC3)
SD.uSD_DETECT: R6.1 ; port SD.uSD_DETECT
NetC181_2: C181.2 C182.2 U24.C2(VDDI)
NetCN1_5: CN1.5(CLK) R13.1 R247.2 U9.1(IO1) U9.10(NC4)
NetCN1_9: CN1.9(CARD_DETECT) R6.2
NetD5_1: D5.1(A) R248.1 U24.K5(RSTn)
NetTP9_1: TP9.1 U24.H5(DS)

Not connected (* = marked no-connect by the designer): CN1 13(NC)*; U8 5(IO4)* 6(NC1)*; U9 5(IO4)* 6(NC1)*

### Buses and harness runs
bus eMMC.SDMMC2_D[0..7]
bus SD.SDMMC1_D[0..3]

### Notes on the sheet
- MICRO SD CARD
- (near R247) 22 ohms to place near MPU
- (near R6) (input with pull up)
- eMMC

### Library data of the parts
C6 = MCD-01356: Capacitor, MLCC, 4.7uF, 6V3, X5R, 20%, 0402, T=0,5mm; Manufacturer_Part_Number: GRM155R60J475ME47; Manufacturer: MURATA; Alternate_Manufacturer_Part_Number: GRM155R60J475ME87; Part_Preference: Recommended; Partial_Alternate_Internal_Part_Number: MCD-04455; Provided_By: SUBCO; ECCN_EU: NEC; ECCN_US: EAR99; Order_Code_RS: 814-5230; Component_Country_Of_Origin: Japan°°; ID: 3456; ShowFields: YES
C8 C177 C179 C182 = MCD-00006: Capacitor, MLCC, 100nF, 16V, X7R, +/-10%, 0402, T=0.5mm; Part_Preference: Recommended; Manufacturer: YAGEO; Manufacturer_Part_Number: CC0402KRX7R7BB104; Alternate_Manufacturer: MURATA; Alternate_Manufacturer_Part_Number: GCM155R71C104KA55D; Partial_Alternate_Internal_Part_Number: MCD-03299; Order_Code_RS: 9402047; Component_Country_Of_Origin: China; ID: 2474; ShowFields: YES
C178 C180 C181 = MCD-02606: Capacitor, MLCC, 2.2uF, 6.3V, X5R, +/-10%, 0402, T=0.5mm; Part_Preference: Recommended; Manufacturer: YAGEO; Manufacturer_Part_Number: CC0402KRX5R5BB225; Order_Code_RS: 1992205; ShowFields: YES; ID: 4712; Component_Country_Of_Origin: China°
CN1 = MCD-00653: Connector_uSD Card, Top Mnt Push-Push; Part_Preference: Recommended; Manufacturer: ATOM; Component_Country_Of_Origin: Unknown; ShowFields: YES; ID: 3087
D5 = MCD-00034: BMS_Part_Number: 9151097; Part_Type: Diode; Part_Preference: Recommended; Manufacturer: STMICROELECTRONICS; Manufacturer_HQ_COO: EU; Component_Country_Of_Origin: China; ShowFields: YES; ID: 2483; Order_Code_RS: 714-6879
HW7 = MCD-03307: MICRO_SD_CARD, SANDISK, 16GB, Class10, 3V; Part_Type: Mechanical; Part_Preference: Recommended; Manufacturer: WESTERN DIGITAL; Manufacturer_Part_Number: SDSDQAD-016G; Order_Code_RS: 220-8618; ShowFields: YES; ID: 5423; Component_Country_Of_Origin: China
R6 = MCD-00052: Resistor,0R,0402,5%,1/16W; Manufacturer_Part_Number: RC0402JR-070RL; Manufacturer: YAGEO; Part_Preference: Recommended; ECCN_US: EAR99; ECCN_EU: NEC; Provided_By: SUBCO; Order_Code_RS: 9232516RL; Component_Country_Of_Origin: China; ID: 2540; ShowFields: YES
R10-R12 R14 R15 = MCD-00063: Resistor,47K,0402,1%,1/16W; Manufacturer_Part_Number: RC0402FR-0747KL; Manufacturer: YAGEO; Part_Preference: Recommended; ECCN_US: EAR99; ECCN_EU: NEC; Provided_By: SUBCO; Order_Code_RS: 9239430; Component_Country_Of_Origin: China; ID: 2528; ShowFields: YES
R13 R37 R44 R49 R248 = MCD-00053: Resistor,10K,0402,1%,1/16W; Manufacturer_Part_Number: RC0402FR-0710KL; Manufacturer: YAGEO; BMS_Part_Number: 9131590; Part_Preference: Recommended; ECCN_US: EAR99; ECCN_EU: NEC; Provided_By: SUBCO; Order_Code_RS: 9239359; Component_Country_Of_Origin: China; ID: 2539; ShowFields: YES
R247 = MCD-02978: Resistor, 22R, 0201, +/-1%, 1/20W; Manufacturer_Part_Number: RC0201FR-0722RL; Manufacturer: YAGEO; Part_Preference: Recommended; Order_Code_RS: 198-7593; ID: 5094; ShowFields: YES; Component_Country_Of_Origin: China
TP9 = MCD-00074: Test Point 1mm; Part_Type: Misc; Part_Preference: Recommended; Component_Country_Of_Origin: Unknown; ID: 2518; ShowFields: YES
U8 U9 = MCD-00667: 4-line ESD protection for high speed lines; Part_Type: Diode; Manufacturer: STMICROELECTRONICS; BMS_Part_Number: 9179041; Manufacturer_HQ_COO: EU; Part_Preference: Recommended; ECCN_US: EAR99; ECCN_EU: NEC; Provided_By: SUBCO with ST control; Component_Country_Of_Origin: Philippines; ID: 3081; ShowFields: YES
U24 = MCD-02799: Memory, eMMC, 4GB, 15nm ,WFBGA , 153 pins; Part_Type: IC; Part_Preference: Not recommended; Manufacturer: KIOXIA; ShowFields: YES; ID: 4911; Component_Country_Of_Origin: Unknown

## Sheet MP257_18x18.SchDoc: STM32MP257  I/Os
size A3; Date: Not used; ApprovedBy: Not used; CheckedBy: Not used; Author: Not used; CompanyName: STMicroelectronics; DrawnBy: Not used; Engineer: Not used; Organization: Not used; Address1: Not used; Address2: Not used; Address3: Not used; Address4: Not used; DocumentNumber: Not used; Revision: Not used; SheetNumber: 3; SheetTotal: 18
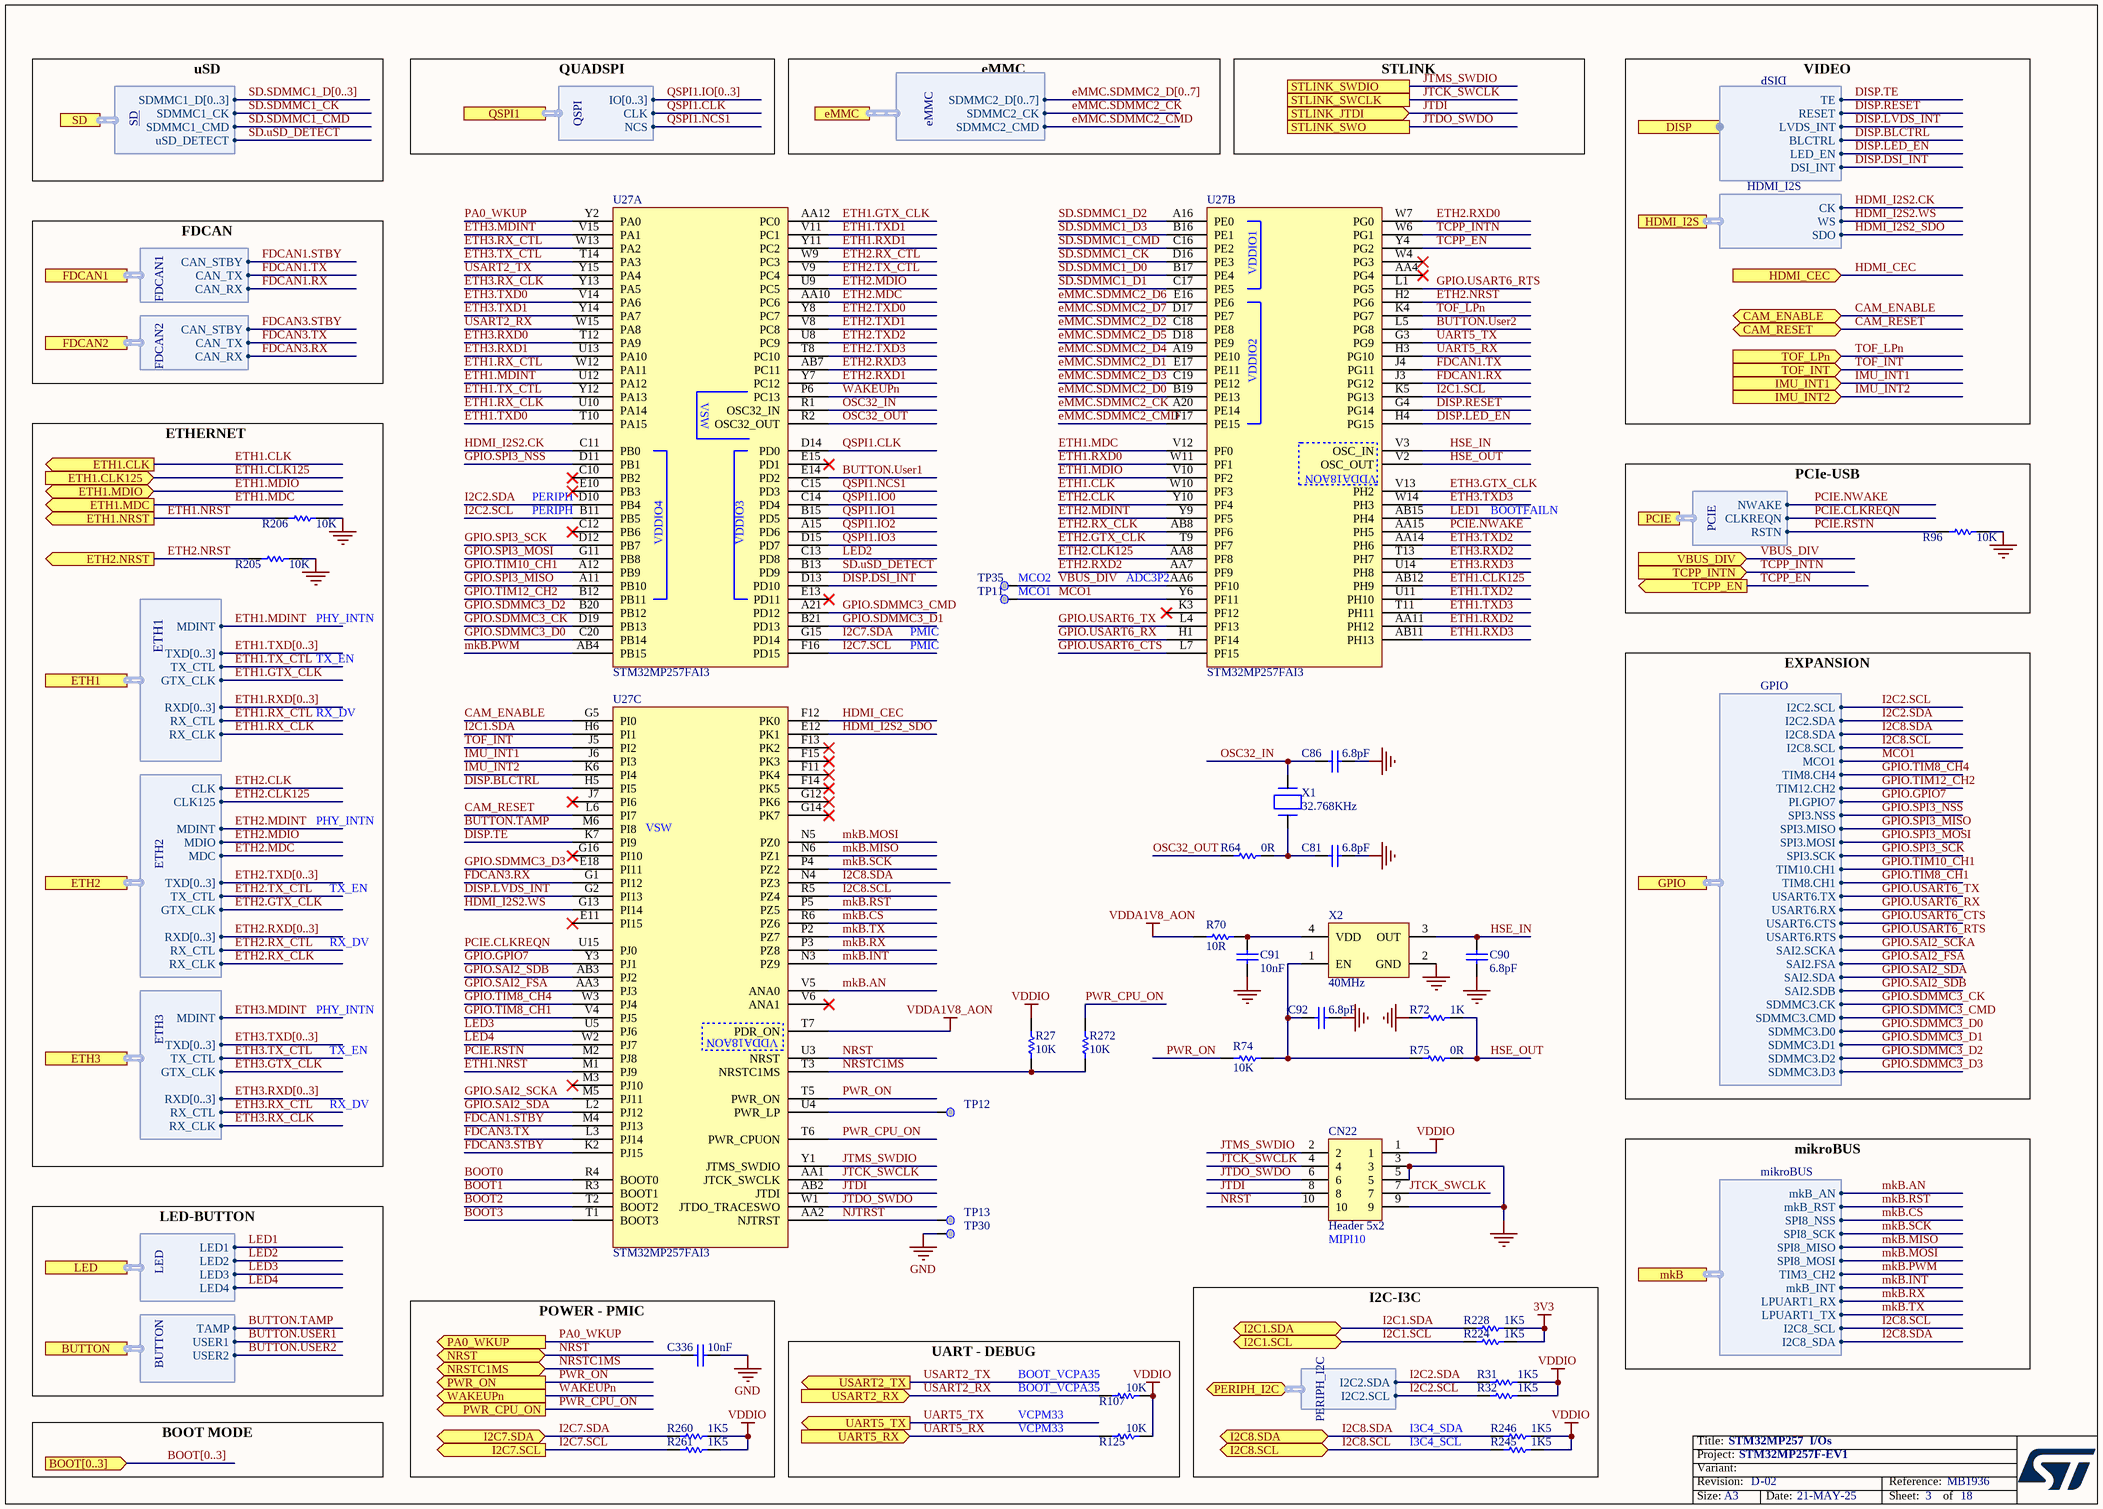
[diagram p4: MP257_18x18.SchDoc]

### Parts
C81  value 6.8pF  [C0402]  (hidden comment: Capacitor)
C86  value 6.8pF  [C0402]  (hidden comment: Capacitor)
C90  value 6.8pF  [C0402]  (hidden comment: Capacitor)
C91  value 10nF  [C0402]  (hidden comment: Capacitor)
C92  value 6.8pF  [C0402]  (hidden comment: Capacitor)
C336  value 10nF  [C0402]  (hidden comment: Capacitor)
CN22  Header 5x2  [CON_SAMTEC_FTSH-105-01-L-DV-K]
R27  value 10K  [R0402]  (hidden comment: Resistor)
R31  value 1K5  [R0402]  (hidden comment: Resistor)
R32  value 1K5  [R0402]  (hidden comment: Resistor)
R64  value 0R  [R0402]
R70  value 10R  [R0402]  (hidden comment: Resistor)
R72  value 1K  [R0402]
R74  value 10K  [R0402]  (hidden comment: Resistor)
R75  value 0R  [R0402]
R96  value 10K  [R0402]  (hidden comment: Resistor)
R107  value 10K  [R0402]  (hidden comment: Resistor)
R125  value 10K  [R0402]  (hidden comment: Resistor)
R205  value 10K  [R0402]  (hidden comment: Resistor)
R206  value 10K  [R0402]  (hidden comment: Resistor)
R224  value 1K5  [R0402]  (hidden comment: Resistor)
R228  value 1K5  [R0402]  (hidden comment: Resistor)
R245  value 1K5  [R0402]  (hidden comment: Resistor)
R246  value 1K5  [R0402]  (hidden comment: Resistor)
R260  value 1K5  [R0402]  (hidden comment: Resistor)
R261  value 1K5  [R0402]  (hidden comment: Resistor)
R272  value 10K  [R0402]  (hidden comment: Resistor)
TP11  Test Point  [TP_SMD_1MM]  (value not drawn)  (no BOM)
TP12  Test Point  [TP_SMD_1MM]  (value not drawn)  (no BOM)
TP13  Test Point  [TP_SMD_1MM]  (value not drawn)  (no BOM)
TP30  Test Point  [TP_SMD_1MM]  (value not drawn)  (no BOM)
TP35  Test Point  [TP_SMD_1MM]  (value not drawn)  (no BOM)
U27  STM32MP257FAI3  [ICC_LFBGA436_18X18_P080_H1P70_STM32MP257_CODE-B0D1]  (parts A,B,C of 9)
X1  value 32.768KHz  [CRY_NX2012SA_2P]  (hidden comment: XTAL_2_PINS)
X2  value 40MHz  [CRY_NZ1612SH_4P]  (hidden comment: OSCILLATOR_4_PINS)

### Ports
BOOT[0..3] (in), BUTTON (harness BUTTON), CAM_ENABLE (bidir), CAM_RESET (bidir), DISP (harness DISP), eMMC (harness eMMC), ETH1 (harness ETH1), ETH1.CLK125 (in), ETH1.CLK (out), ETH1.MDC (out), ETH1.MDIO (bidir), ETH1.NRST (out), ETH2 (harness ETH2), ETH2.NRST (out), ETH3 (harness ETH3), FDCAN1 (harness FDCAN1), FDCAN2 (harness FDCAN2), GPIO (harness GPIO), HDMI_CEC (in), HDMI_I2S (harness HDMI_I2S), I2C1.SCL (bidir), I2C1.SDA (bidir), I2C7.SCL (out), I2C7.SDA (bidir), I2C8.SCL (bidir), I2C8.SDA (bidir), IMU_INT1 (in), IMU_INT2 (in), LED (harness LED), mkB (harness mikroBUS), NRST (bidir), NRSTC1MS (bidir), PA0_WKUP (out), PCIE (harness PCIE), PERIPH_I2C (bidir, harness PERIPH_I2C), PWR_CPU_ON (out), PWR_ON (out), QSPI1 (harness QSPI), SD (harness SD), STLINK_JTDI (in), STLINK_SWCLK, STLINK_SWDIO, STLINK_SWO, TCPP_EN (out), TCPP_INTN (in), TOF_INT (in), TOF_LPn (in), UART5_RX (in), UART5_TX (out), USART2_RX (in), USART2_TX (out), VBUS_DIV (in), WAKEUPn (out)

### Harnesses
ETH2: MDINT, CLK125, TXD[0..3], MDIO, MDC, RX_CLK, GTX_CLK, TX_CTL, RXD[0..3], RX_CTL, CLK
ETH3: MDINT, TXD[0..3], RX_CLK, GTX_CLK, TX_CTL, RXD[0..3], RX_CTL
ETH1: MDINT, TXD[0..3], RX_CLK, GTX_CLK, TX_CTL, RXD[0..3], RX_CTL
HDMI_I2S: CK, SDO, WS
QSPI: IO[0..3], CLK, NCS
GPIO: I2C2.SCL, I2C2.SDA, I2C8.SDA, MCO1, TIM8.CH4, TIM12.CH2, PI.GPIO7, SPI3.NSS, SPI3.MISO, SPI3.MOSI, SPI3.SCK, TIM10.CH1, TIM8.CH1, USART6.TX, USART6.RX, USART6.CTS, USART6.RTS, SDMMC3.CK, SDMMC3.CMD, SDMMC3.D0, SDMMC3.D1, SDMMC3.D2, SDMMC3.D3, I2C8.SCL, SAI2.SCKA, SAI2.FSA, SAI2.SDA, SAI2.SDB
PERIPH_I2C: I2C2.SDA, I2C2.SCL
PCIE: NWAKE, CLKREQN, RSTN
SD: SDMMC1_D[0..3], SDMMC1_CK, SDMMC1_CMD, uSD_DETECT
FDCAN1: CAN_STBY, CAN_TX, CAN_RX
FDCAN2: CAN_STBY, CAN_TX, CAN_RX
LED: LED1, LED2, LED3, LED4
BUTTON: TAMP, USER1, USER2
eMMC: SDMMC2_CK, SDMMC2_CMD, SDMMC2_D[0..7]
mikroBUS: I2C8_SDA, SPI8_NSS, SPI8_MISO, SPI8_MOSI, SPI8_SCK, TIM3_CH2, LPUART1_RX, I2C8_SCL, LPUART1_TX, mkB_INT, mkB_RST, mkB_AN
DISP: RESET, TE, LVDS_INT, BLCTRL, LED_EN, DSI_INT

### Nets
3V3: R224.2 R228.2
GND: C81.2 C86.2 C90.1 C91.1 C92.2 C336.1 CN22.3 CN22.5 CN22.9 R72.2 R96.2 R205.2 R206.2 TP30.1 X2.2(GND)
VDDA1V8_AON: R70.1 U27.T7(PDR_ON)
VDDIO: CN22.1 R27.2 R31.2 R32.2 R107.2 R125.2 R245.2 R246.2 R260.2 R261.2
BOOT0: U27.R4(BOOT0)
BOOT1: U27.R3(BOOT1)
BOOT2: U27.T2(BOOT2)
BOOT3: U27.T1(BOOT3)
BUTTON.TAMP: U27.M6(PI8) ; port BUTTON.TAMP
BUTTON.User1: U27.E14(PD2) ; port BUTTON.USER1
BUTTON.User2: U27.L5(PG8) ; port BUTTON.USER2
CAM_ENABLE: U27.G5(PI0) ; port CAM_ENABLE
CAM_RESET: U27.L6(PI7) ; port CAM_RESET
DISP.BLCTRL: U27.H5(PI5) ; port DISP.BLCTRL
DISP.DSI_INT: U27.D13(PD10) ; port DISP.DSI_INT
DISP.LED_EN: U27.H4(PG15) ; port DISP.LED_EN
DISP.LVDS_INT: U27.G2(PI13) ; port DISP.LVDS_INT
DISP.RESET: U27.G4(PG14) ; port DISP.RESET
DISP.TE: U27.K7(PI9) ; port DISP.TE
eMMC.SDMMC2_CK: U27.A20(PE14) ; port eMMC.SDMMC2_CK
eMMC.SDMMC2_CMD: U27.F17(PE15) ; port eMMC.SDMMC2_CMD
eMMC.SDMMC2_D0: U27.B19(PE13)
eMMC.SDMMC2_D1: U27.E17(PE11)
eMMC.SDMMC2_D2: U27.C18(PE8)
eMMC.SDMMC2_D3: U27.C19(PE12)
eMMC.SDMMC2_D4: U27.A19(PE10)
eMMC.SDMMC2_D5: U27.D18(PE9)
eMMC.SDMMC2_D6: U27.E16(PE6)
eMMC.SDMMC2_D7: U27.D17(PE7)
ETH1.CLK: U27.W10(PF3) ; port ETH1.CLK
ETH1.CLK125: U27.AB12(PH9) ; port ETH1.CLK125
ETH1.GTX_CLK: U27.AA12(PC0) ; port ETH1.GTX_CLK
ETH1.MDC: U27.V12(PF0) ; port ETH1.MDC
ETH1.MDINT: U27.U12(PA12) ; port ETH1.MDINT
ETH1.MDIO: U27.V10(PF2) ; port ETH1.MDIO
ETH1.NRST: R206.1 U27.M1(PJ9) ; port ETH1.NRST
ETH1.RX_CLK: U27.U10(PA14) ; port ETH1.RX_CLK
ETH1.RX_CTL: U27.W12(PA11) ; port ETH1.RX_CTL
ETH1.RXD0: U27.W11(PF1)
ETH1.RXD1: U27.Y11(PC2)
ETH1.RXD2: U27.AA11(PH12)
ETH1.RXD3: U27.AB11(PH13)
ETH1.TX_CTL: U27.Y12(PA13) ; port ETH1.TX_CTL
ETH1.TXD0: U27.T10(PA15)
ETH1.TXD1: U27.V11(PC1)
ETH1.TXD2: U27.U11(PH10)
ETH1.TXD3: U27.T11(PH11)
ETH2.CLK: U27.Y10(PF4) ; port ETH2.CLK
ETH2.CLK125: U27.AA8(PF8) ; port ETH2.CLK125
ETH2.GTX_CLK: U27.T9(PF7) ; port ETH2.GTX_CLK
ETH2.MDC: U27.AA10(PC6) ; port ETH2.MDC
ETH2.MDINT: U27.Y9(PF5) ; port ETH2.MDINT
ETH2.MDIO: U27.U9(PC5) ; port ETH2.MDIO
ETH2.NRST: R205.1 U27.H2(PG6) ; port ETH2.NRST
ETH2.RX_CLK: U27.AB8(PF6) ; port ETH2.RX_CLK
ETH2.RX_CTL: U27.W9(PC3) ; port ETH2.RX_CTL
ETH2.RXD0: U27.W7(PG0)
ETH2.RXD1: U27.Y7(PC12)
ETH2.RXD2: U27.AA7(PF9)
ETH2.RXD3: U27.AB7(PC11)
ETH2.TX_CTL: U27.V9(PC4) ; port ETH2.TX_CTL
ETH2.TXD0: U27.Y8(PC7)
ETH2.TXD1: U27.V8(PC8)
ETH2.TXD2: U27.U8(PC9)
ETH2.TXD3: U27.T8(PC10)
ETH3.GTX_CLK: U27.V13(PH2) ; port ETH3.GTX_CLK
ETH3.MDINT: U27.V15(PA1) ; port ETH3.MDINT
ETH3.RX_CLK: U27.Y13(PA5) ; port ETH3.RX_CLK
ETH3.RX_CTL: U27.W13(PA2) ; port ETH3.RX_CTL
ETH3.RXD0: U27.T12(PA9)
ETH3.RXD1: U27.U13(PA10)
ETH3.RXD2: U27.T13(PH7)
ETH3.RXD3: U27.U14(PH8)
ETH3.TX_CTL: U27.T14(PA3) ; port ETH3.TX_CTL
ETH3.TXD0: U27.V14(PA6)
ETH3.TXD1: U27.Y14(PA7)
ETH3.TXD2: U27.AA14(PH6)
ETH3.TXD3: U27.W14(PH3)
FDCAN1.RX: U27.J3(PG12) ; port FDCAN1.CAN_RX
FDCAN1.STBY: U27.M4(PJ13) ; port FDCAN1.CAN_STBY
FDCAN1.TX: U27.J4(PG11) ; port FDCAN1.CAN_TX
FDCAN3.RX: U27.G1(PI12) ; port FDCAN2.CAN_RX
FDCAN3.STBY: U27.K2(PJ15) ; port FDCAN2.CAN_STBY
FDCAN3.TX: U27.L3(PJ14) ; port FDCAN2.CAN_TX
GPIO.GPIO7: U27.Y3(PJ1) ; port GPIO.PI.GPIO7  [project net EXP_GPIO7]
GPIO.SAI2_FSA: U27.AA3(PJ3) ; port GPIO.SAI2.FSA  [project net EXP_GPIO19]
GPIO.SAI2_SCKA: U27.M5(PJ11) ; port GPIO.SAI2.SCKA  [project net EXP_GPIO18]
GPIO.SAI2_SDA: U27.L2(PJ12) ; port GPIO.SAI2.SDA  [project net EXP_GPIO20]
GPIO.SAI2_SDB: U27.AB3(PJ2) ; port GPIO.SAI2.SDB  [project net EXP_GPIO21]
GPIO.SDMMC3_CK: U27.D19(PB13) ; port GPIO.SDMMC3.CK
GPIO.SDMMC3_CMD: U27.A21(PD12) ; port GPIO.SDMMC3.CMD  [project net EXP_GPIO23]
GPIO.SDMMC3_D0: U27.C20(PB14) ; port GPIO.SDMMC3.D0  [project net EXP_GPIO24]
GPIO.SDMMC3_D1: U27.B21(PD13) ; port GPIO.SDMMC3.D1  [project net EXP_GPIO25]
GPIO.SDMMC3_D2: U27.B20(PB12) ; port GPIO.SDMMC3.D2  [project net EXP_GPIO26]
GPIO.SDMMC3_D3: U27.E18(PI11) ; port GPIO.SDMMC3.D3  [project net EXP_GPIO27]
GPIO.SPI3_MISO: U27.A11(PB10) ; port GPIO.SPI3.MISO  [project net EXP_GPIO9]
GPIO.SPI3_MOSI: U27.G11(PB8) ; port GPIO.SPI3.MOSI  [project net EXP_GPIO10]
GPIO.SPI3_NSS: U27.D11(PB1) ; port GPIO.SPI3.NSS  [project net EXP_GPIO8]
GPIO.SPI3_SCK: U27.D12(PB7) ; port GPIO.SPI3.SCK  [project net EXP_GPIO11]
GPIO.TIM8_CH1: U27.V4(PJ5) ; port GPIO.TIM8.CH1  [project net EXP_GPIO13]
GPIO.TIM8_CH4: U27.W3(PJ4) ; port GPIO.TIM8.CH4  [project net EXP_GPIO5]
GPIO.TIM10_CH1: U27.A12(PB9) ; port GPIO.TIM10.CH1  [project net EXP_GPIO12]
GPIO.TIM12_CH2: U27.B12(PB11) ; port GPIO.TIM12.CH2  [project net EXP_GPIO6]
GPIO.USART6_CTS: U27.L7(PF15) ; port GPIO.USART6.CTS  [project net EXP_GPIO16]
GPIO.USART6_RTS: U27.L1(PG5) ; port GPIO.USART6.RTS  [project net EXP_GPIO17]
GPIO.USART6_RX: U27.H1(PF14) ; port GPIO.USART6.RX  [project net EXP_GPIO15]
GPIO.USART6_TX: U27.L4(PF13) ; port GPIO.USART6.TX  [project net EXP_GPIO14]
HDMI_CEC: U27.F12(PK0) ; port HDMI_CEC
HDMI_I2S2.CK: U27.C11(PB0) ; port HDMI_I2S.CK
HDMI_I2S2.WS: U27.G13(PI14) ; port HDMI_I2S.WS
HDMI_I2S2_SDO: U27.E12(PK1) ; port HDMI_I2S.SDO
HSE_IN: C90.2 U27.V3(OSC_IN) X2.3(OUT)
HSE_OUT: R72.1 R75.2 U27.V2(OSC_OUT)
I2C1.SCL: R224.1 U27.K5(PG13) ; port I2C1.SCL
I2C1.SDA: R228.1 U27.H6(PI1) ; port I2C1.SDA
I2C2.SCL: R32.1 U27.B11(PB5) ; port GPIO.I2C2.SCL, port PERIPH_I2C.I2C2.SCL
I2C2.SDA: R31.1 U27.D10(PB4) ; port GPIO.I2C2.SDA, port PERIPH_I2C.I2C2.SDA
I2C7.SCL: R261.1 U27.F16(PD15) ; port I2C7.SCL
I2C7.SDA: R260.1 U27.G15(PD14) ; port I2C7.SDA
I2C8.SCL: R245.1 U27.R5(PZ4) ; port I2C8.SCL, port GPIO.I2C8.SCL, port mkB.I2C8_SCL  [project net EXP_GPIO3]
I2C8.SDA: R246.1 U27.N4(PZ3) ; port I2C8.SDA, port GPIO.I2C8.SDA, port mkB.I2C8_SDA  [project net EXP_GPIO2]
IMU_INT1: U27.J6(PI3) ; port IMU_INT1
IMU_INT2: U27.K6(PI4) ; port IMU_INT2
JTCK_SWCLK: CN22.4 CN22.7 U27.AA1(JTCK_SWCLK) ; port STLINK_SWCLK
JTDI: CN22.8 U27.AB2(JTDI) ; port STLINK_JTDI
JTDO_SWDO: CN22.6 U27.W1(JTDO_TRACESWO) ; port STLINK_SWO
JTMS_SWDIO: CN22.2 U27.Y1(JTMS_SWDIO) ; port STLINK_SWDIO
LED1: U27.AB15(PH4) ; port LED.LED1
LED2: U27.C13(PD8) ; port LED.LED2
LED3: U27.U5(PJ6) ; port LED.LED3
LED4: U27.W2(PJ7) ; port LED.LED4
MCO1: TP11.1 U27.Y6(PF11) ; port GPIO.MCO1  [project net EXP_GPIO4]
mkB.AN: U27.V5(ANA0) ; port mkB.mkB_AN
mkB.CS: U27.R6(PZ6) ; port mkB.SPI8_NSS
mkB.INT: U27.N3(PZ9) ; port mkB.mkB_INT
mkB.MISO: U27.N6(PZ1) ; port mkB.SPI8_MISO
mkB.MOSI: U27.N5(PZ0) ; port mkB.SPI8_MOSI
mkB.PWM: U27.AB4(PB15) ; port mkB.TIM3_CH2
mkB.RST: U27.P5(PZ5) ; port mkB.mkB_RST
mkB.RX: U27.P3(PZ8) ; port mkB.LPUART1_RX
mkB.SCK: U27.P4(PZ2) ; port mkB.SPI8_SCK
mkB.TX: U27.P2(PZ7) ; port mkB.LPUART1_TX
NJTRST: TP13.1 U27.AA2(NJTRST)
NRST: C336.2 CN22.10 U27.U3(NRST) ; port NRST
NRSTC1MS: R27.1 R272.1 U27.T3(NRSTC1MS) ; port NRSTC1MS
OSC32_IN: C86.1 U27.R1(OSC32_IN) X1.2(X2)
OSC32_OUT: R64.1 U27.R2(OSC32_OUT)
PA0_WKUP: U27.Y2(PA0) ; port PA0_WKUP
PCIE.CLKREQN: U27.U15(PJ0) ; port PCIE.CLKREQN
PCIE.NWAKE: U27.AA15(PH5) ; port PCIE.NWAKE
PCIE.RSTN: R96.1 U27.M2(PJ8) ; port PCIE.RSTN
PWR_CPU_ON: R272.2 U27.T6(PWR_CPUON) ; port PWR_CPU_ON
PWR_ON: R74.2 U27.T5(PWR_ON) ; port PWR_ON
QSPI1.CLK: U27.D14(PD0) ; port QSPI1.CLK
QSPI1.IO0: U27.C14(PD4)
QSPI1.IO1: U27.B15(PD5)
QSPI1.IO2: U27.A15(PD6)
QSPI1.IO3: U27.D15(PD7)
QSPI1.NCS1: U27.C15(PD3) ; port QSPI1.NCS
SD.SDMMC1_CK: U27.D16(PE3) ; port SD.SDMMC1_CK
SD.SDMMC1_CMD: U27.C16(PE2) ; port SD.SDMMC1_CMD
SD.SDMMC1_D0: U27.B17(PE4)
SD.SDMMC1_D1: U27.C17(PE5)
SD.SDMMC1_D2: U27.A16(PE0)
SD.SDMMC1_D3: U27.B16(PE1)
SD.uSD_DETECT: U27.B13(PD9) ; port SD.uSD_DETECT
TCPP_EN: U27.Y4(PG2) ; port TCPP_EN
TCPP_INTN: U27.W6(PG1) ; port TCPP_INTN
TOF_INT: U27.J5(PI2) ; port TOF_INT
TOF_LPn: U27.K4(PG7) ; port TOF_LPn
UART5_RX: R125.1 U27.H3(PG10) ; port UART5_RX
UART5_TX: U27.G3(PG9) ; port UART5_TX
USART2_RX: R107.1 U27.W15(PA8) ; port USART2_RX
USART2_TX: U27.Y15(PA4) ; port USART2_TX
VBUS_DIV: TP35.1 U27.AA6(PF10) ; port VBUS_DIV
WAKEUPn: U27.P6(PC13) ; port WAKEUPn
NetC81_1: C81.1 R64.2 X1.1(X1)
NetC91_2: C91.2 R70.2 X2.4(VDD)
NetC92_1: C92.1 R74.1 R75.1 X2.1(EN)
NetTP12_1: TP12.1 U27.U4(PWR_LP)

Not connected (* = marked no-connect by the designer): U27 AA4(PG4)* C10(PB2)* C12(PB6)* E10(PB3)* E11(PI15)* E13(PD11)* E15(PD1)* F11(PK4)* F13(PK2)* F14(PK5)* F15(PK3)* G12(PK6)* G14(PK7)* G16(PI10)* J7(PI6)* K3(PF12)* M3(PJ10)* V6(ANA1)* W4(PG3)*

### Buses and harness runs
bus BOOT[0..3] = port BOOT[0..3]
bus eMMC.SDMMC2_D[0..7]
bus ETH1.RXD[0..3]
bus ETH1.TXD[0..3]
bus ETH2.RXD[0..3]
bus ETH2.TXD[0..3]
bus ETH3.RXD[0..3]
bus ETH3.TXD[0..3]
bus QSPI1.IO[0..3]
bus SD.SDMMC1_D[0..3]

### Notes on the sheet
- uSD
- QUADSPI
- eMMC
- STLINK
- FDCAN
- VIDEO
- (near U27) PERIPH
- BOOTFAILN
- MCO2
- (near U27) ADC3P2
- PHY_INTN
- PMIC
- MCO1
- (near R96) PCIe-USB
- RX_DV
- TX_EN
- EXPANSION
- ETHERNET
- (near CN22) MIPI10
- LED-BUTTON
- (near R107) BOOT_VCPA35
- mikroBUS
- VCPM33
- I3C4_SDA
- I3C4_SCL
- BOOT MODE
- POWER - PMIC
- UART - DEBUG
- I2C-I3C

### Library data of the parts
C81 C86 = MCD-00674: Capacitor, MLCC, 6.8pF, 50V, NPO, +-0.25pF, 0402, T=0.5mm; Manufacturer_Part_Number: CC0402CRNPO9BN6R8; Manufacturer: YAGEO; Part_Preference: Recommended; Provided_By: SUBCO; Initial_Board_Reference: MB1319; Path: ws/MCD_ApplicationBoards/Lists/MCDPARTSdatabase; Item Type: Item; Component_Country_Of_Origin: China; ID: 3068; ShowFields: YES
C90 C92 = MCD-00674: Capacitor, MLCC, 6.8pF, 50V, NPO, +-0.25pF, 0402, T=0.5mm; Manufacturer_Part_Number: CC0402CRNPO9BN6R8; Manufacturer: YAGEO; Part_Preference: Recommended; Provided_By: SUBCO; Initial_Board_Reference: MB1319; Component_Country_Of_Origin: China; ID: 3068; ShowFields: YES
C91 C336 = MCD-00011: Capacitor, MLCC, 10nF, 16V, X7R, 10%, 0402, T=0.5mm; Manufacturer_Part_Number: CC0402KRX7R7BB103; Manufacturer: YAGEO; Part_Preference: Recommended; Provided_By: SUBCO; Initial_Board_Reference: MB1274; Order_Code_RS: 3019275; Component_Country_Of_Origin: China; ID: 2469; ShowFields: YES
CN22 = MCD-01951: Header, 5x2, 1.27mm, VR, SMD, T=5.97mm; Part_Type: Connector; Part_Preference: Recommended; Manufacturer: SAMTEC; Manufacturer_Part_Number: FTSH-105-01-L-DV-K-A; Partial_Alternate_Internal_Part_Number: MCD-04427; Order_Code_RS: 159-2343; Component_Country_Of_Origin: China, Costa Rica, Malaysia, USA, Vietnam; ShowFields: YES; ID: 4051
R27 R74 R107 R125 R272 = MCD-00053: Resistor,10K,0402,1%,1/16W; BMS_Part_Number: 9131590; Part_Preference: Recommended; Manufacturer: YAGEO; Manufacturer_Part_Number: RC0402FR-0710KL; Order_Code_RS: 9239359; Component_Country_Of_Origin: China; ID: 2539; ShowFields: YES
R31 R32 R224 R228 R245 R246 R260 R261 = MCD-00068: Resistor,1K5,0402,1%,1/16W; Part_Preference: Recommended; Manufacturer: YAGEO; Manufacturer_Part_Number: RC0402FR-071K5L; Order_Code_RS: 9239251; Component_Country_Of_Origin: China; ID: 2524; ShowFields: YES
R64 R75 = MCD-00052: Resistor,0R,0402,5%,1/16W; Manufacturer_Part_Number: RC0402JR-070RL; Manufacturer: YAGEO; Part_Preference: Recommended; Provided_By: SUBCO; Initial_Board_Reference: mb1274; Order_Code_RS: 9232516RL; Component_Country_Of_Origin: China; ID: 2540; ShowFields: YES
R70 = MCD-00358: Resistor,10R,0402,1%,1/16W; Manufacturer_Part_Number: RC0402FR-0710RL; Manufacturer: YAGEO; Part_Preference: Recommended; Provided_By: SUBCO; Order_Code_RS: 618-5848; Component_Country_Of_Origin: China; ID: 2919; ShowFields: YES
R72 = MCD-00061: Resistor,1K,0402,1%,1/16W; Manufacturer_Part_Number: RC0402FR-071KL; Manufacturer: YAGEO; Part_Preference: Recommended; Provided_By: SUBCO; Initial_Board_Reference: mb1274; Order_Code_RS: 9239235; Component_Country_Of_Origin: China; ID: 2532; ShowFields: YES
R96 R205 R206 = MCD-00053: Resistor,10K,0402,1%,1/16W; Manufacturer_Part_Number: RC0402FR-0710KL; Manufacturer: YAGEO; BMS_Part_Number: 9131590; Part_Preference: Recommended; Order_Code_RS: 9239359; Component_Country_Of_Origin: China; ID: 2539; ShowFields: YES
TP11-TP13 TP30 TP35 = MCD-00074: Test Point 1mm; Part_Type: Misc; Part_Preference: Recommended; Initial_Board_Reference: MB1274; Component_Country_Of_Origin: Unknown; ID: 2518; ShowFields: YES
U27 = MCD-02000: as U27 on sheet Video
X1 = MCD-01479: Crystal, 32.768kHz, 6pF, +/-20ppm, 80K, 2.05x1.2mm; BMS_Part_Number: 9157049; Part_Type: Crystal_Osc; Part_Preference: Recommended; Manufacturer: NDK; Manufacturer_Part_Number: NX2012SA-32.768KHZ-EXS00A-MU00527; Component_Country_Of_Origin: Japan; ShowFields: YES; ID: 3579
X2 = MCD-02343: Oscillator, SPXO, 40Mhz, +/-50ppm, 1.8V, square wave, 1.6x1.2mm; Part_Type: Crystal_Osc; Part_Preference: Recommended; Manufacturer: NDK; Manufacturer_Part_Number: NZ1612SH-40MHz-END5951A; Component_Country_Of_Origin: Japan; ID: 4449; ShowFields: YES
